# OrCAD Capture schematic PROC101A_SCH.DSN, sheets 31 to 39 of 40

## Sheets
31 40. HARDWARE SCHEMATICS: title: HARDWARE SCHEMATICS
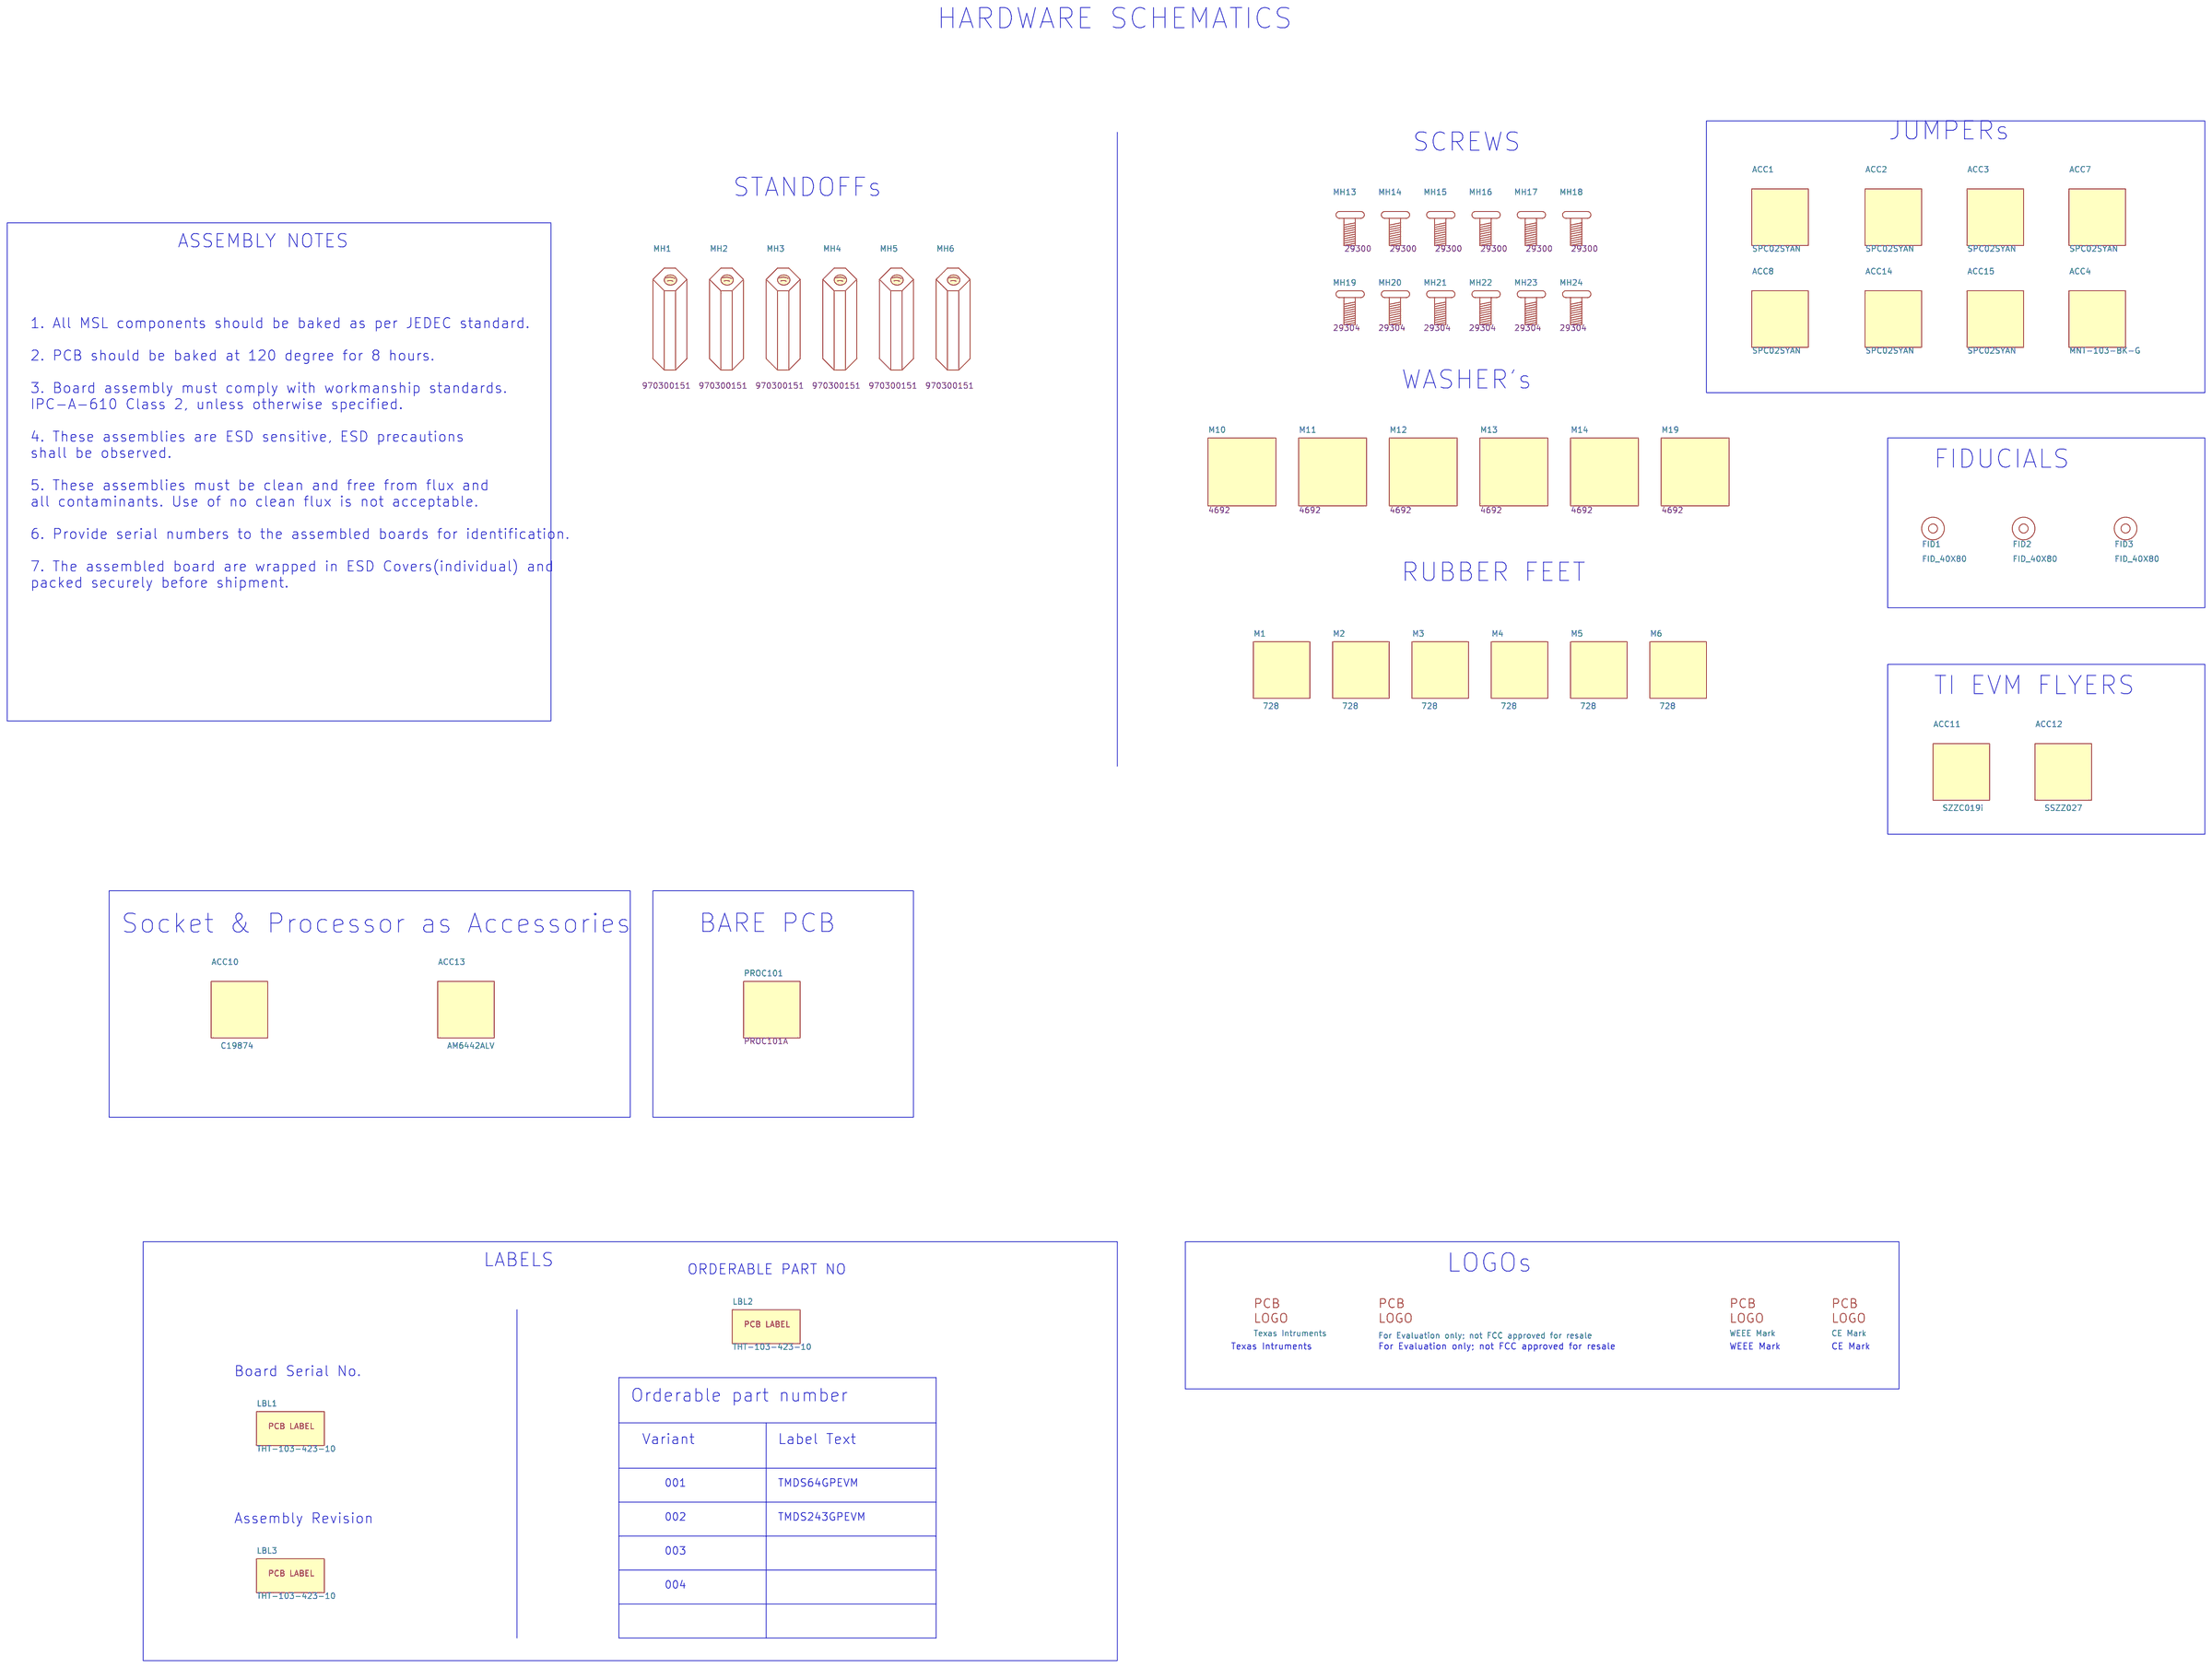
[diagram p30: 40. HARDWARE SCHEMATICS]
32 07. GPIO MAPPING TABLE: title: GPIO  MAPPING TABLE
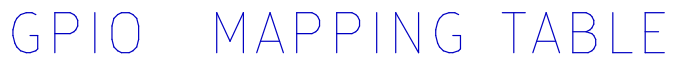
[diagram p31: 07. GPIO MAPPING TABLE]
33 08. I2C TREE: title: I2C TREE
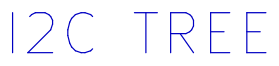
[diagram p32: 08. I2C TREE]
34 06. POWER SEQUENCE: title: POWER SEQUENCE
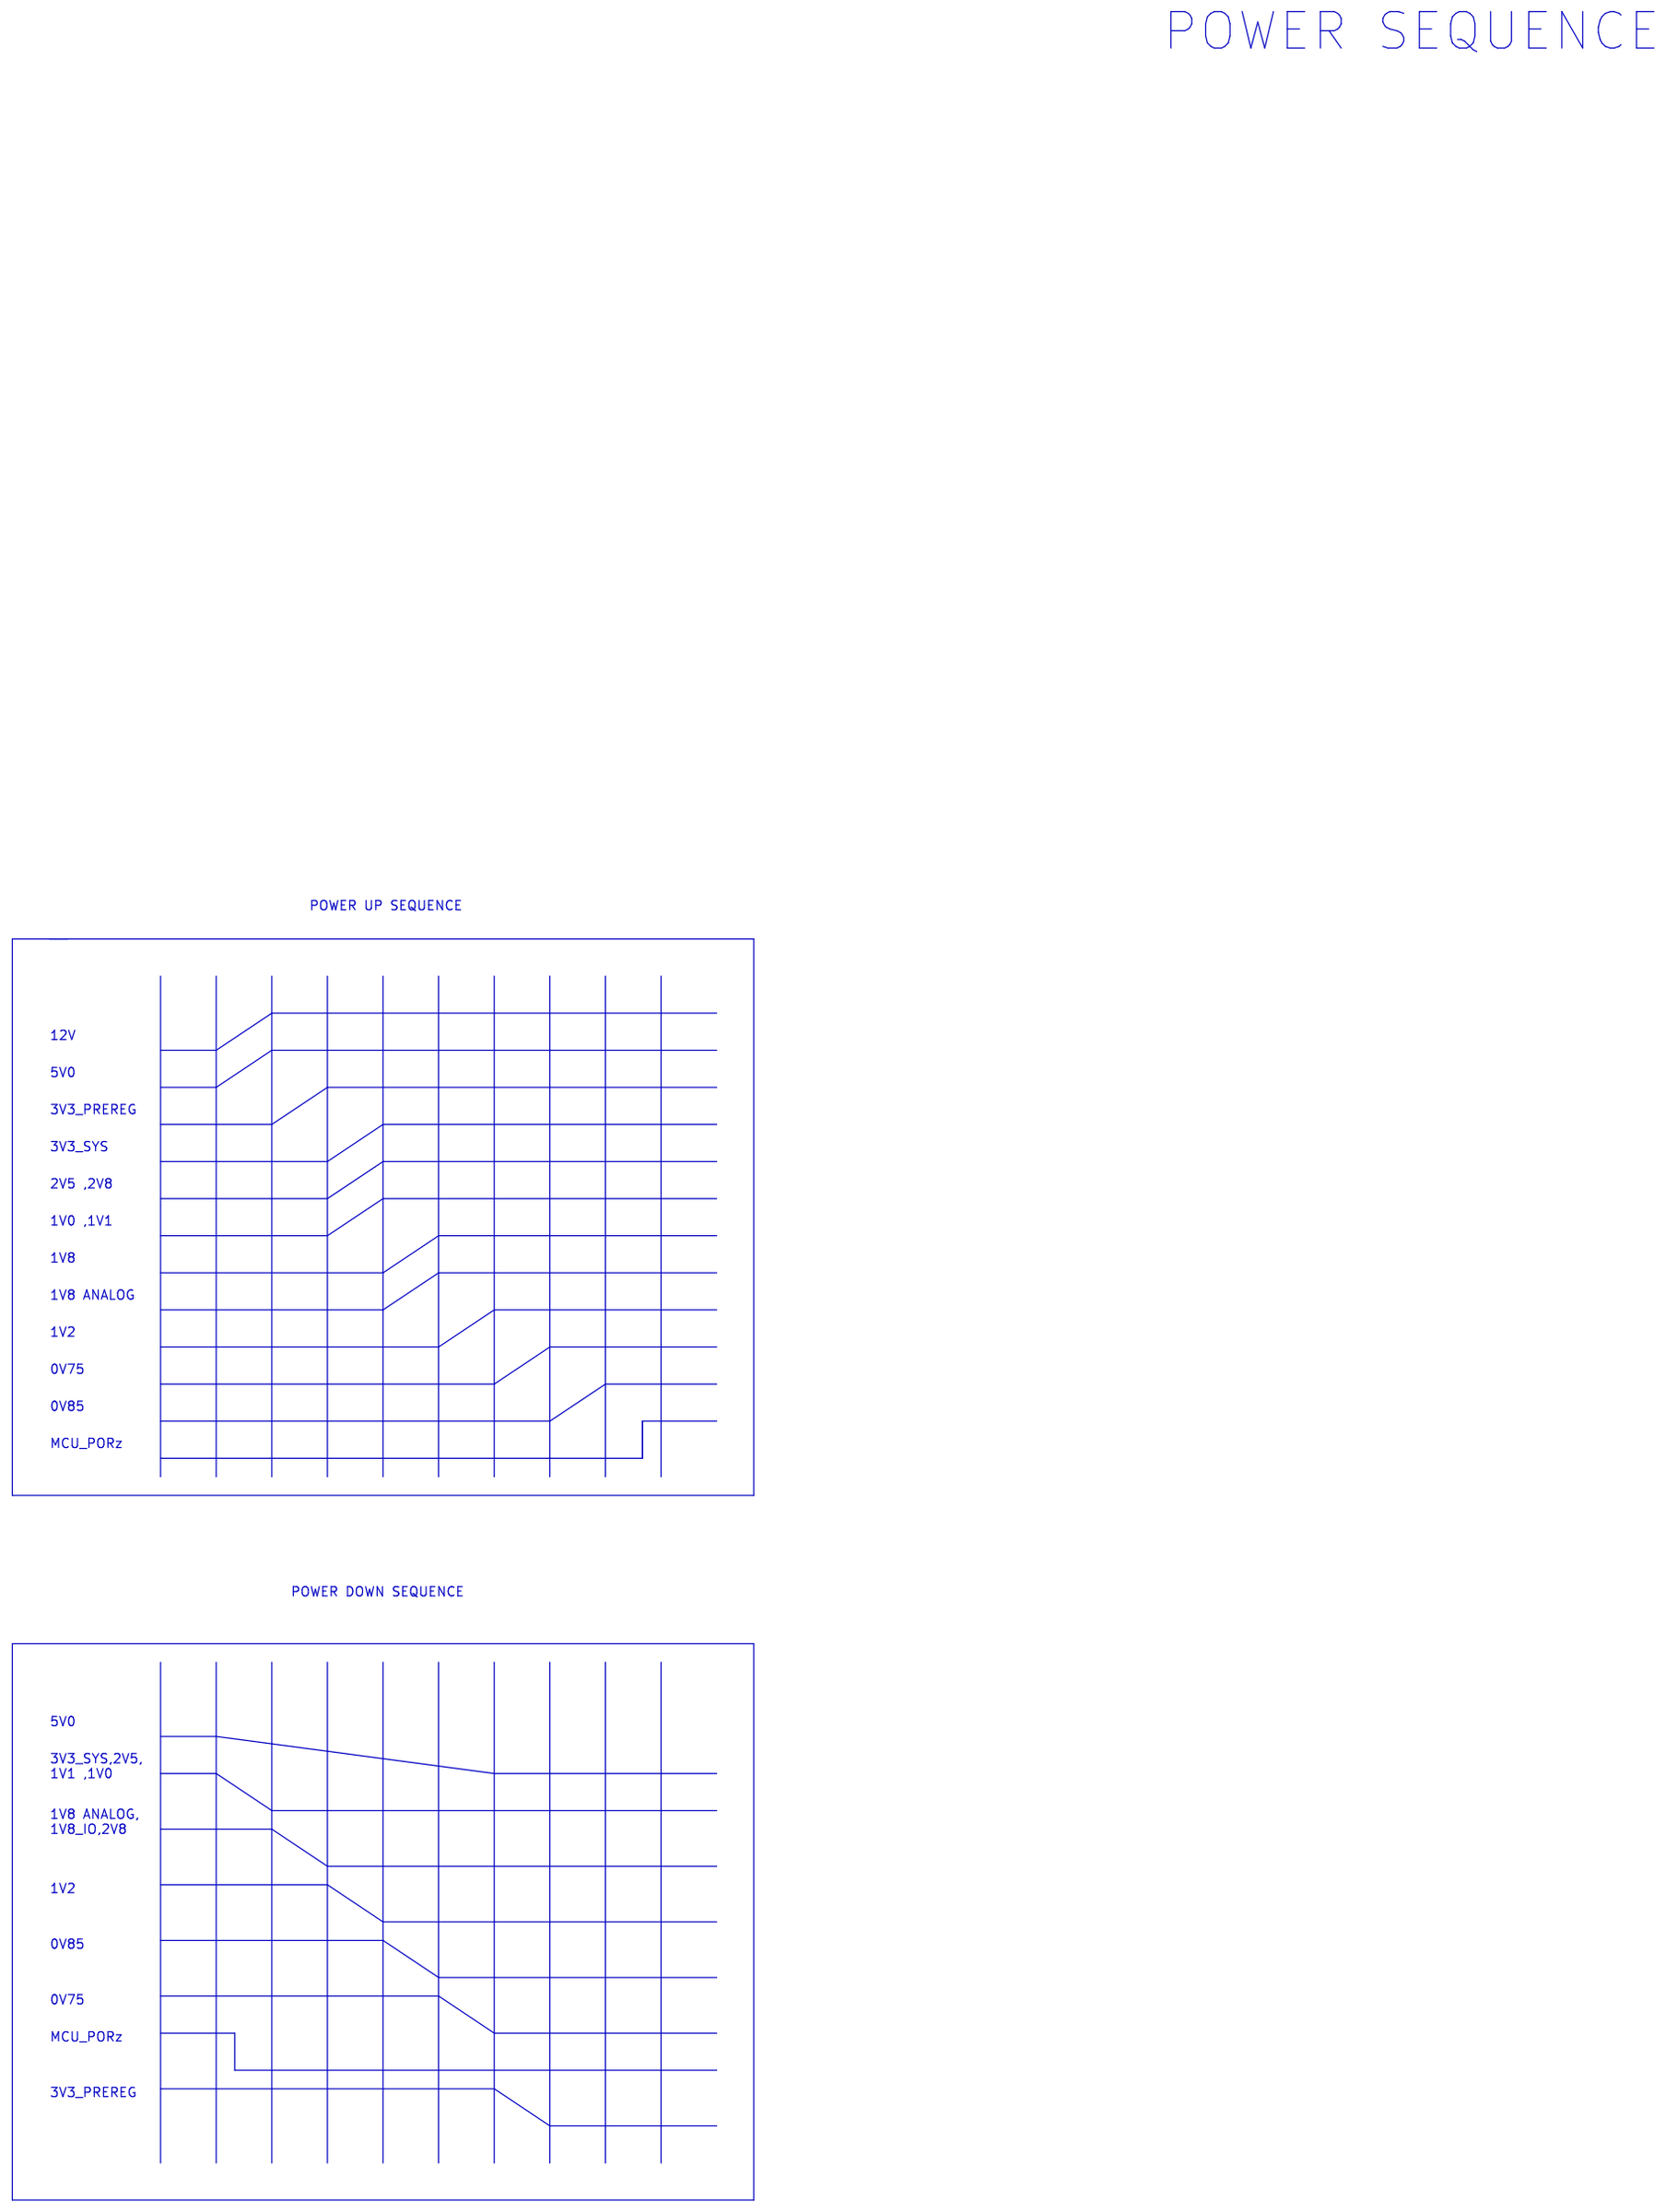
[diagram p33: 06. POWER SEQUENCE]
35 05. POWER FLOW DIAGRAM: title: POWER FLOW DIAGRAM
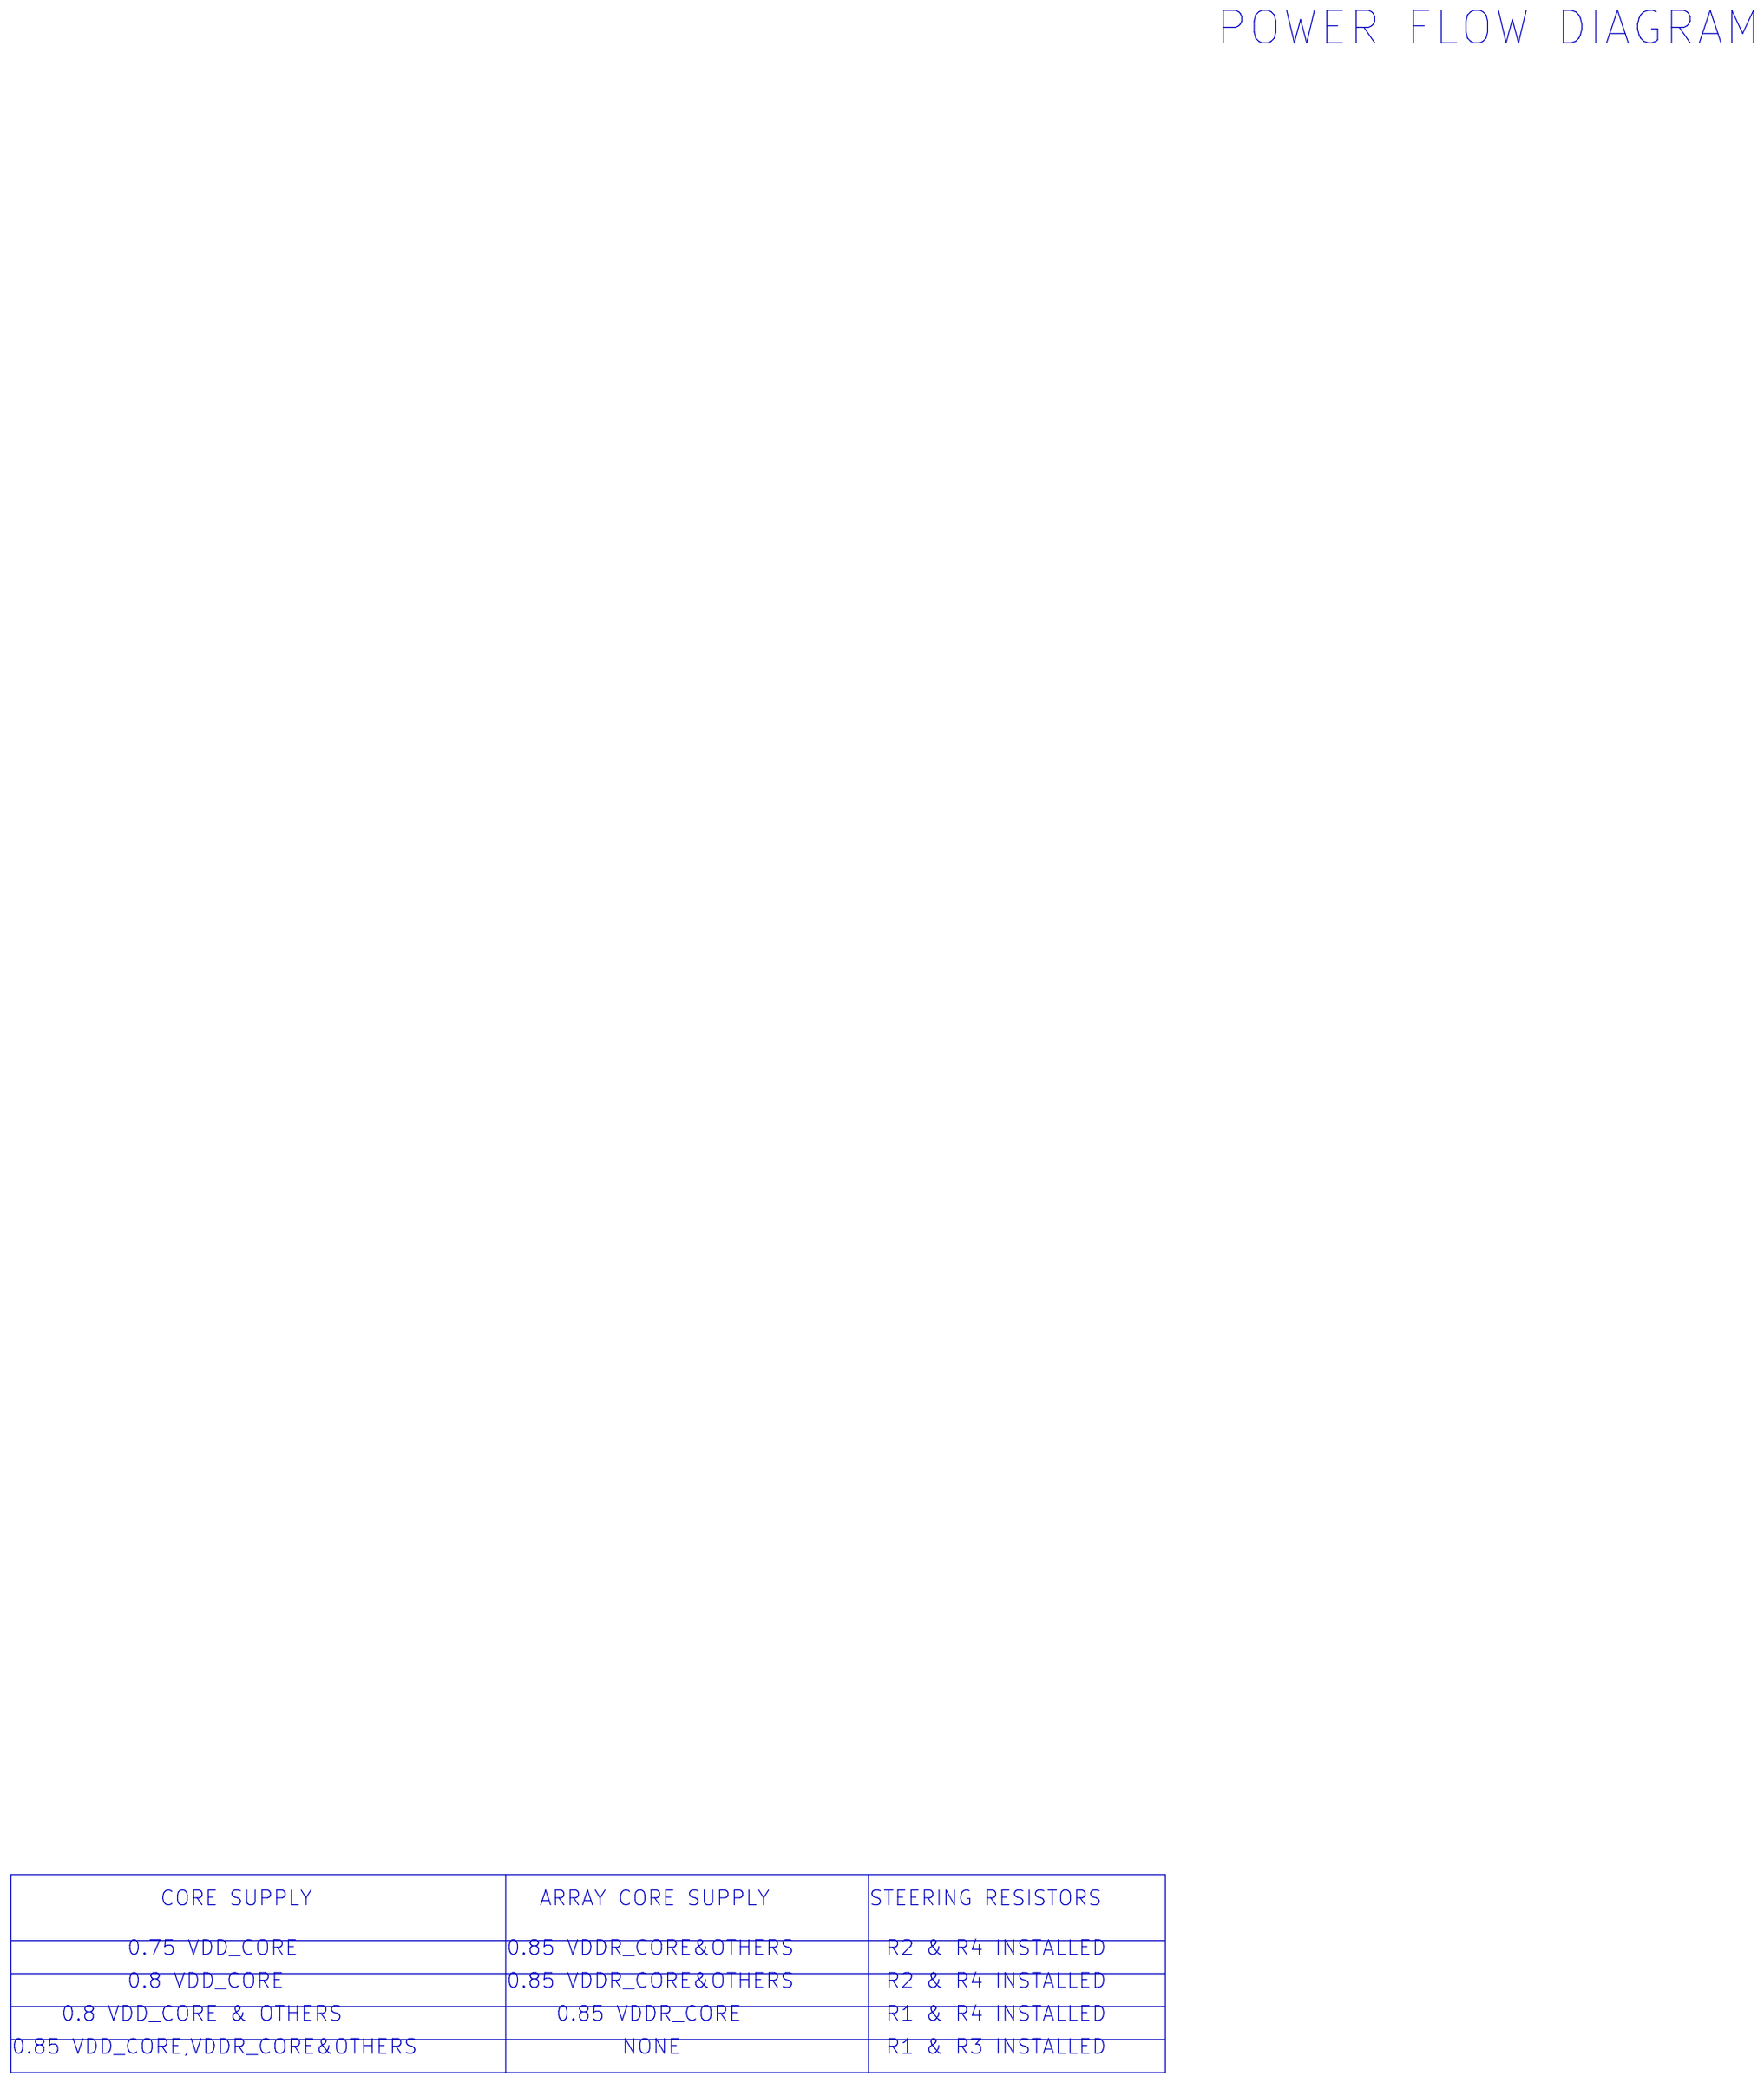
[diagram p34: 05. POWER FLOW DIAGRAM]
36 03.BLOCK_DIAGRAM_AM64x_EVM: title: BLOCK DIAGRAM_CP BOARD
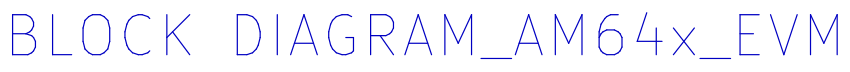
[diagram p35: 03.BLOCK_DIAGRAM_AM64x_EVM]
37 01. TABLE OF CONTENTS: title: TABLE OF CONTENTS
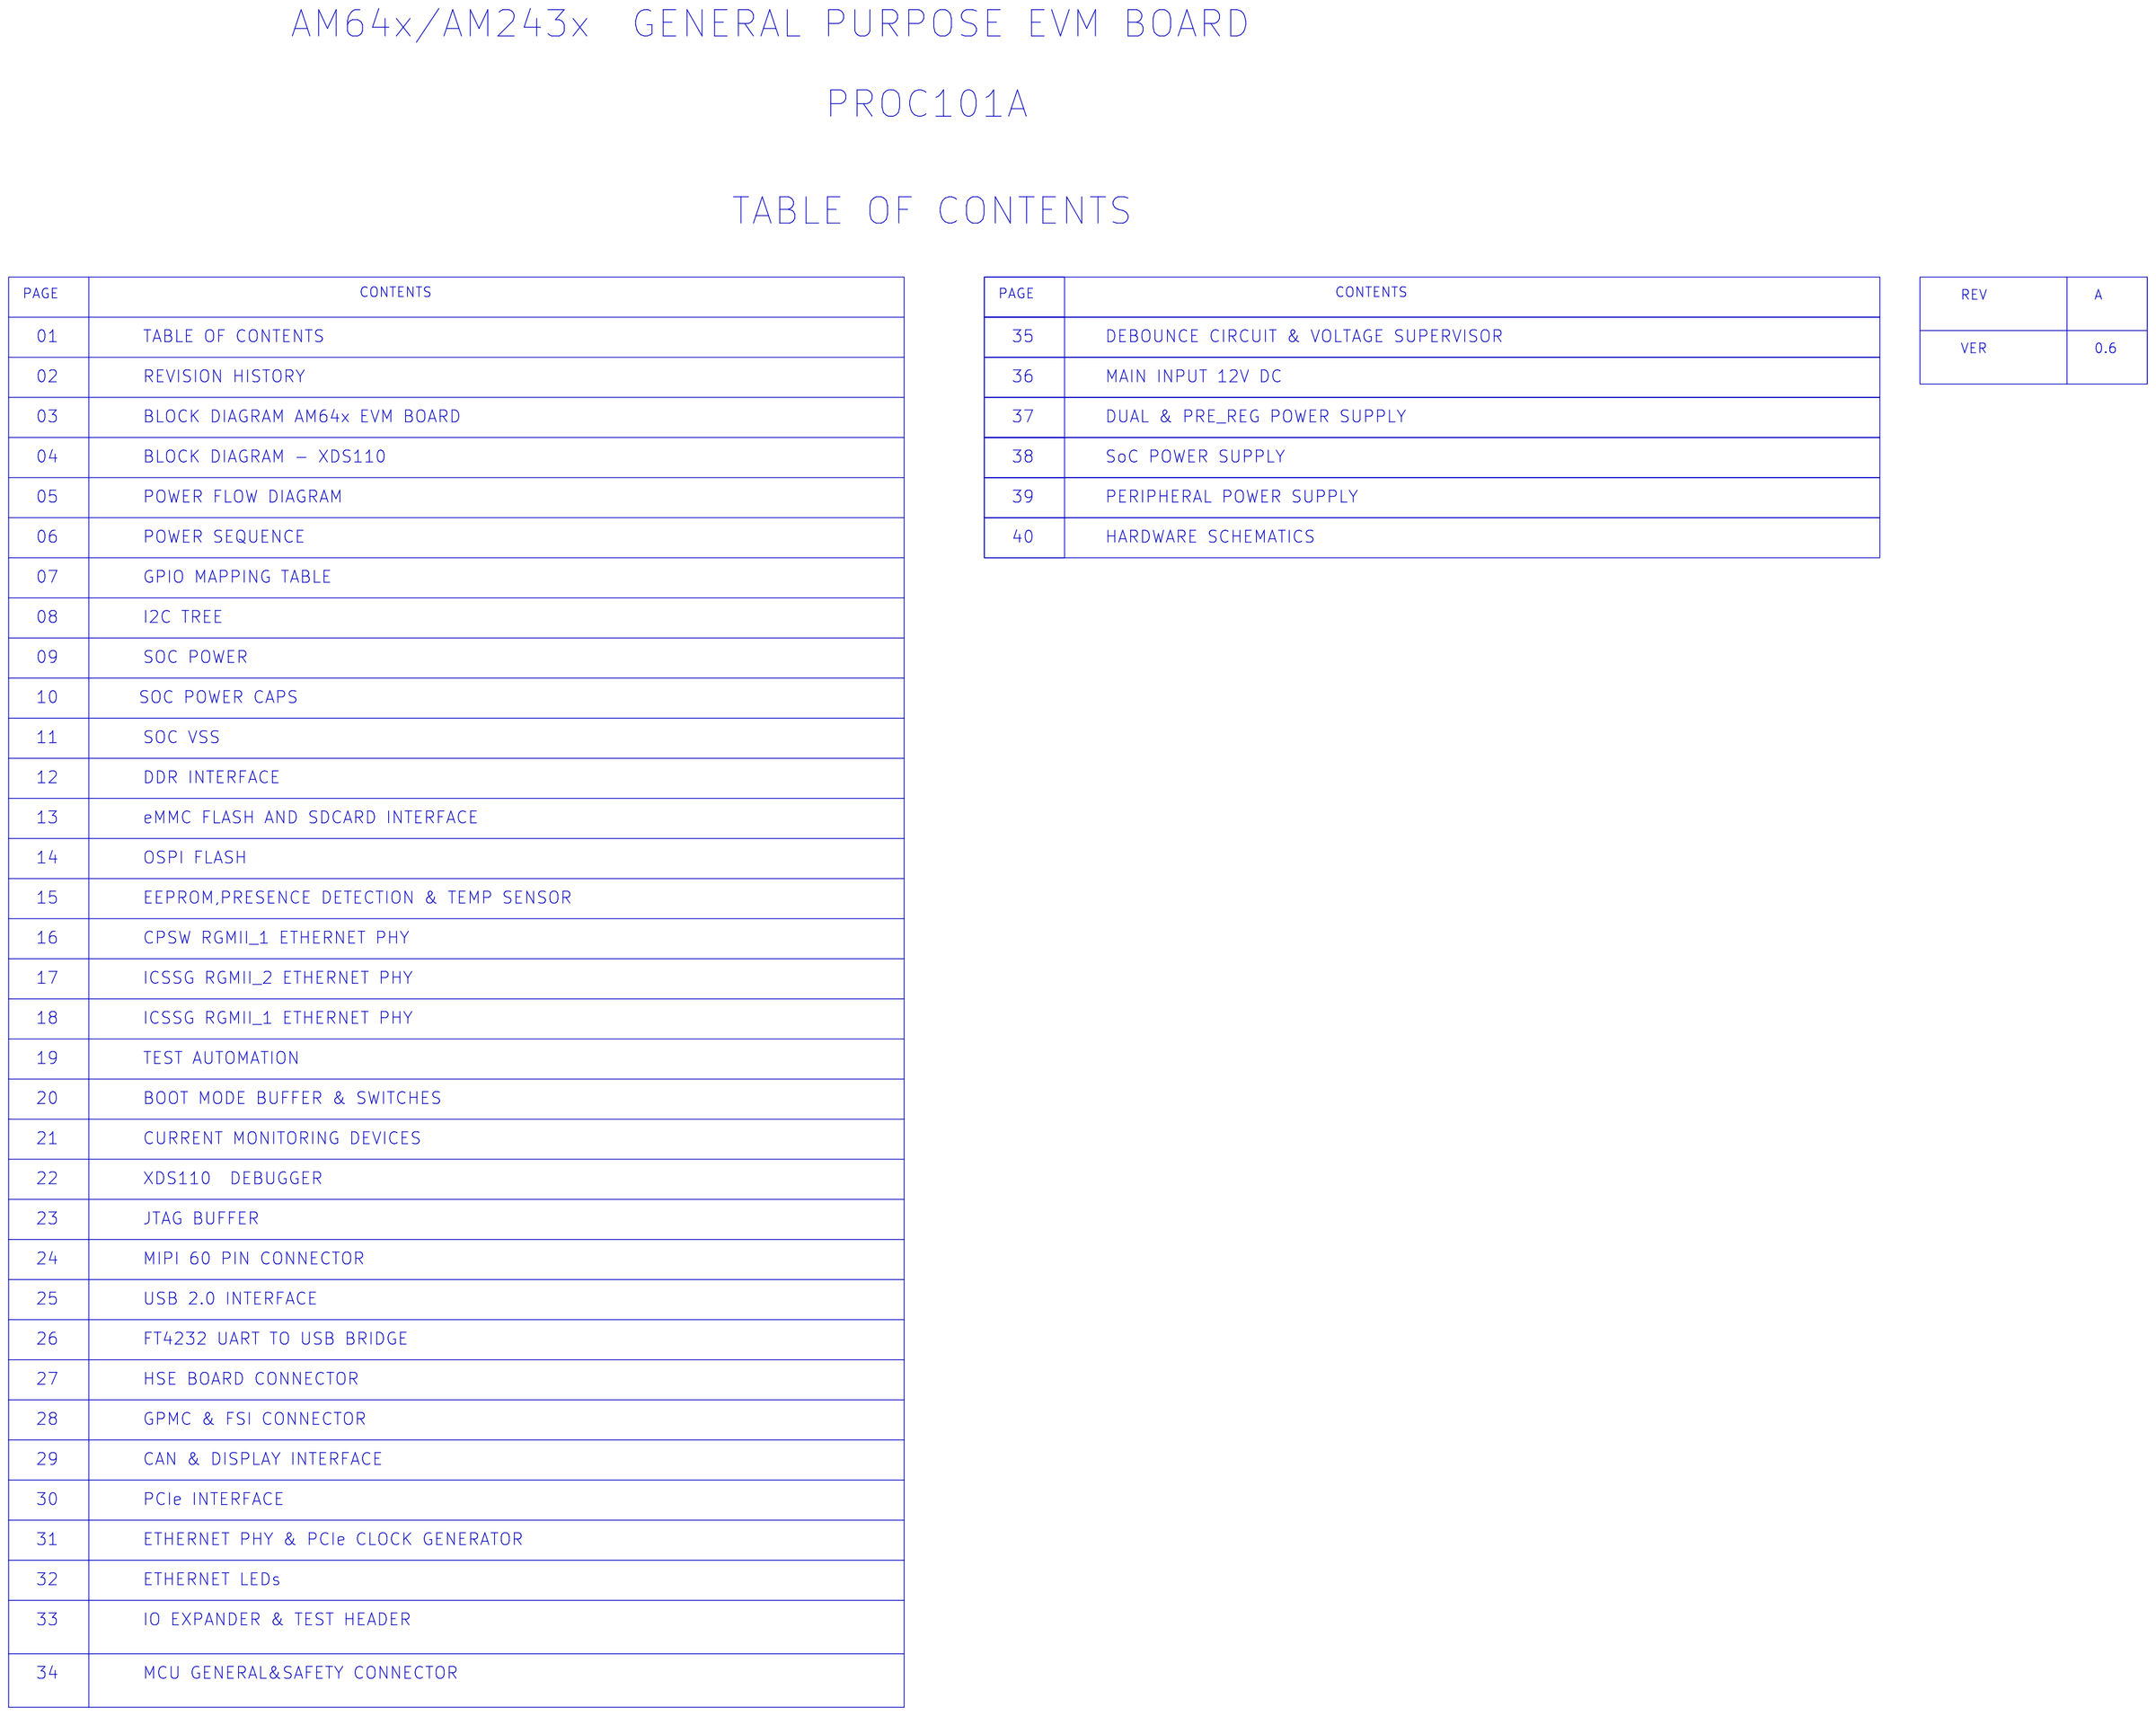
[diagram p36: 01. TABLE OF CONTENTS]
38 02. REVISION HISTORY: title: REVISION HISTORY
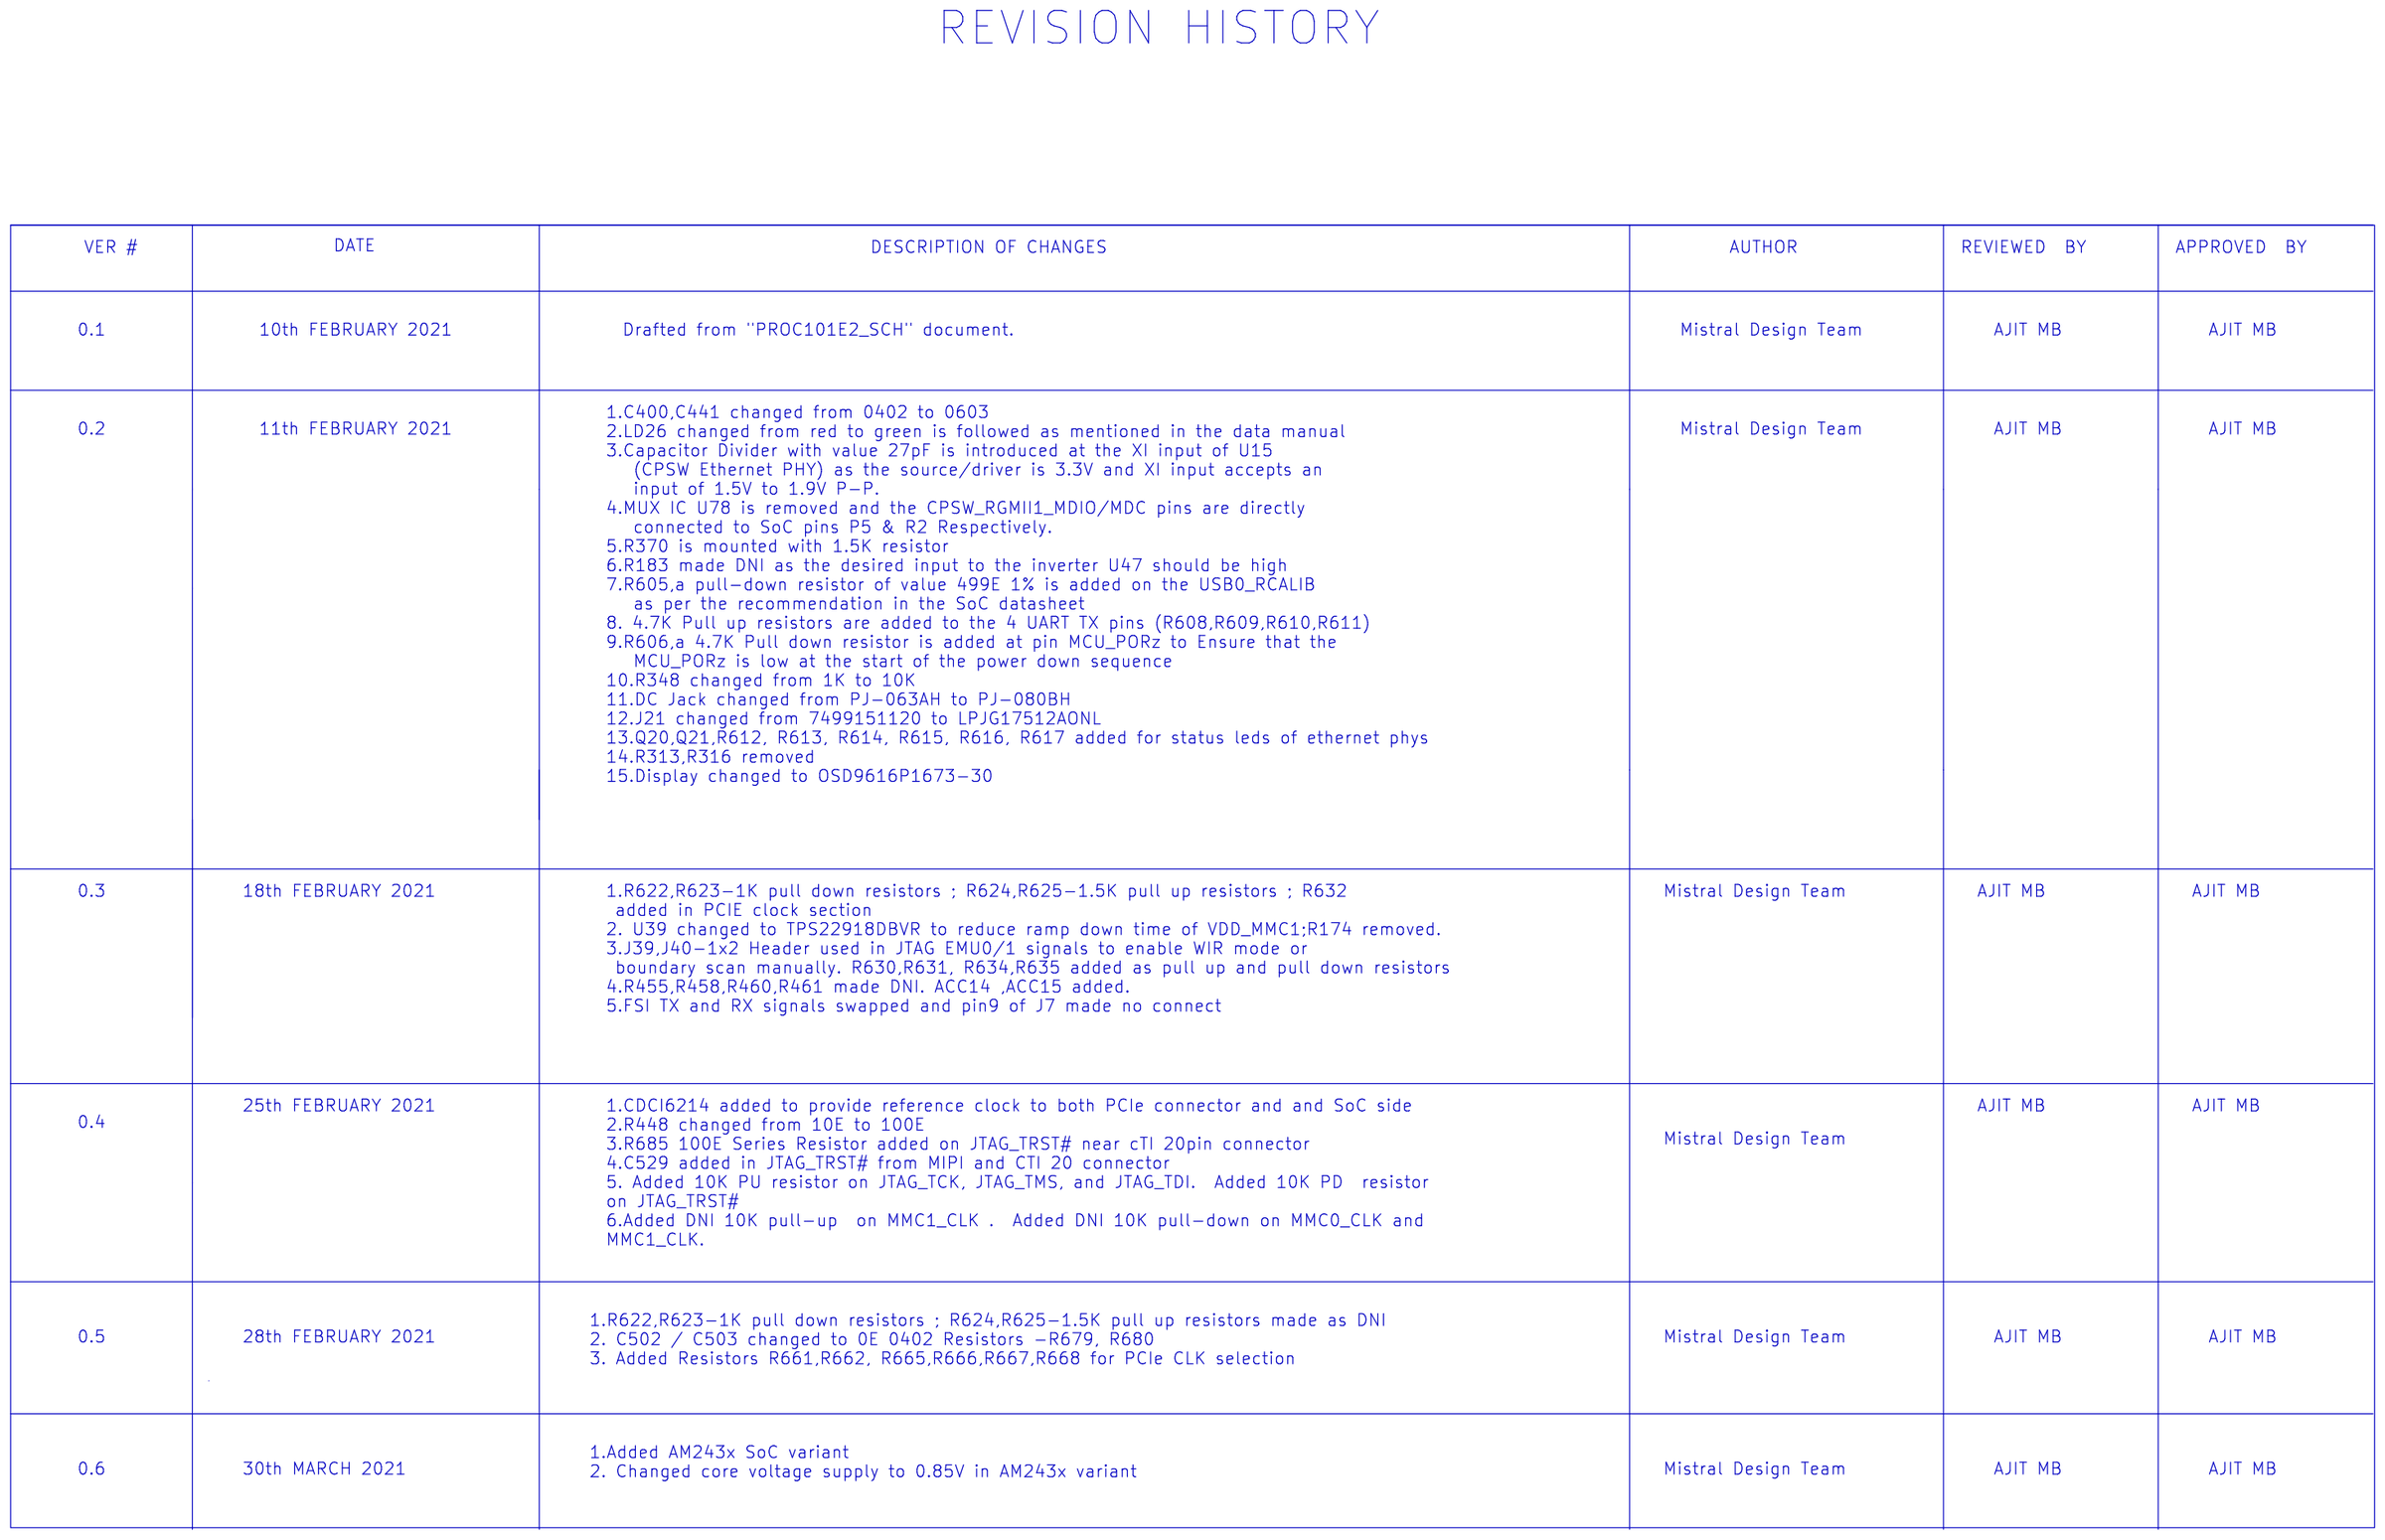
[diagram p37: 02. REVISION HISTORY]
39 17. ICSSG RGMII_2 ETHERNET PHY: size C; title: ICSSG1 RGMII_2 ETHERNET PHY
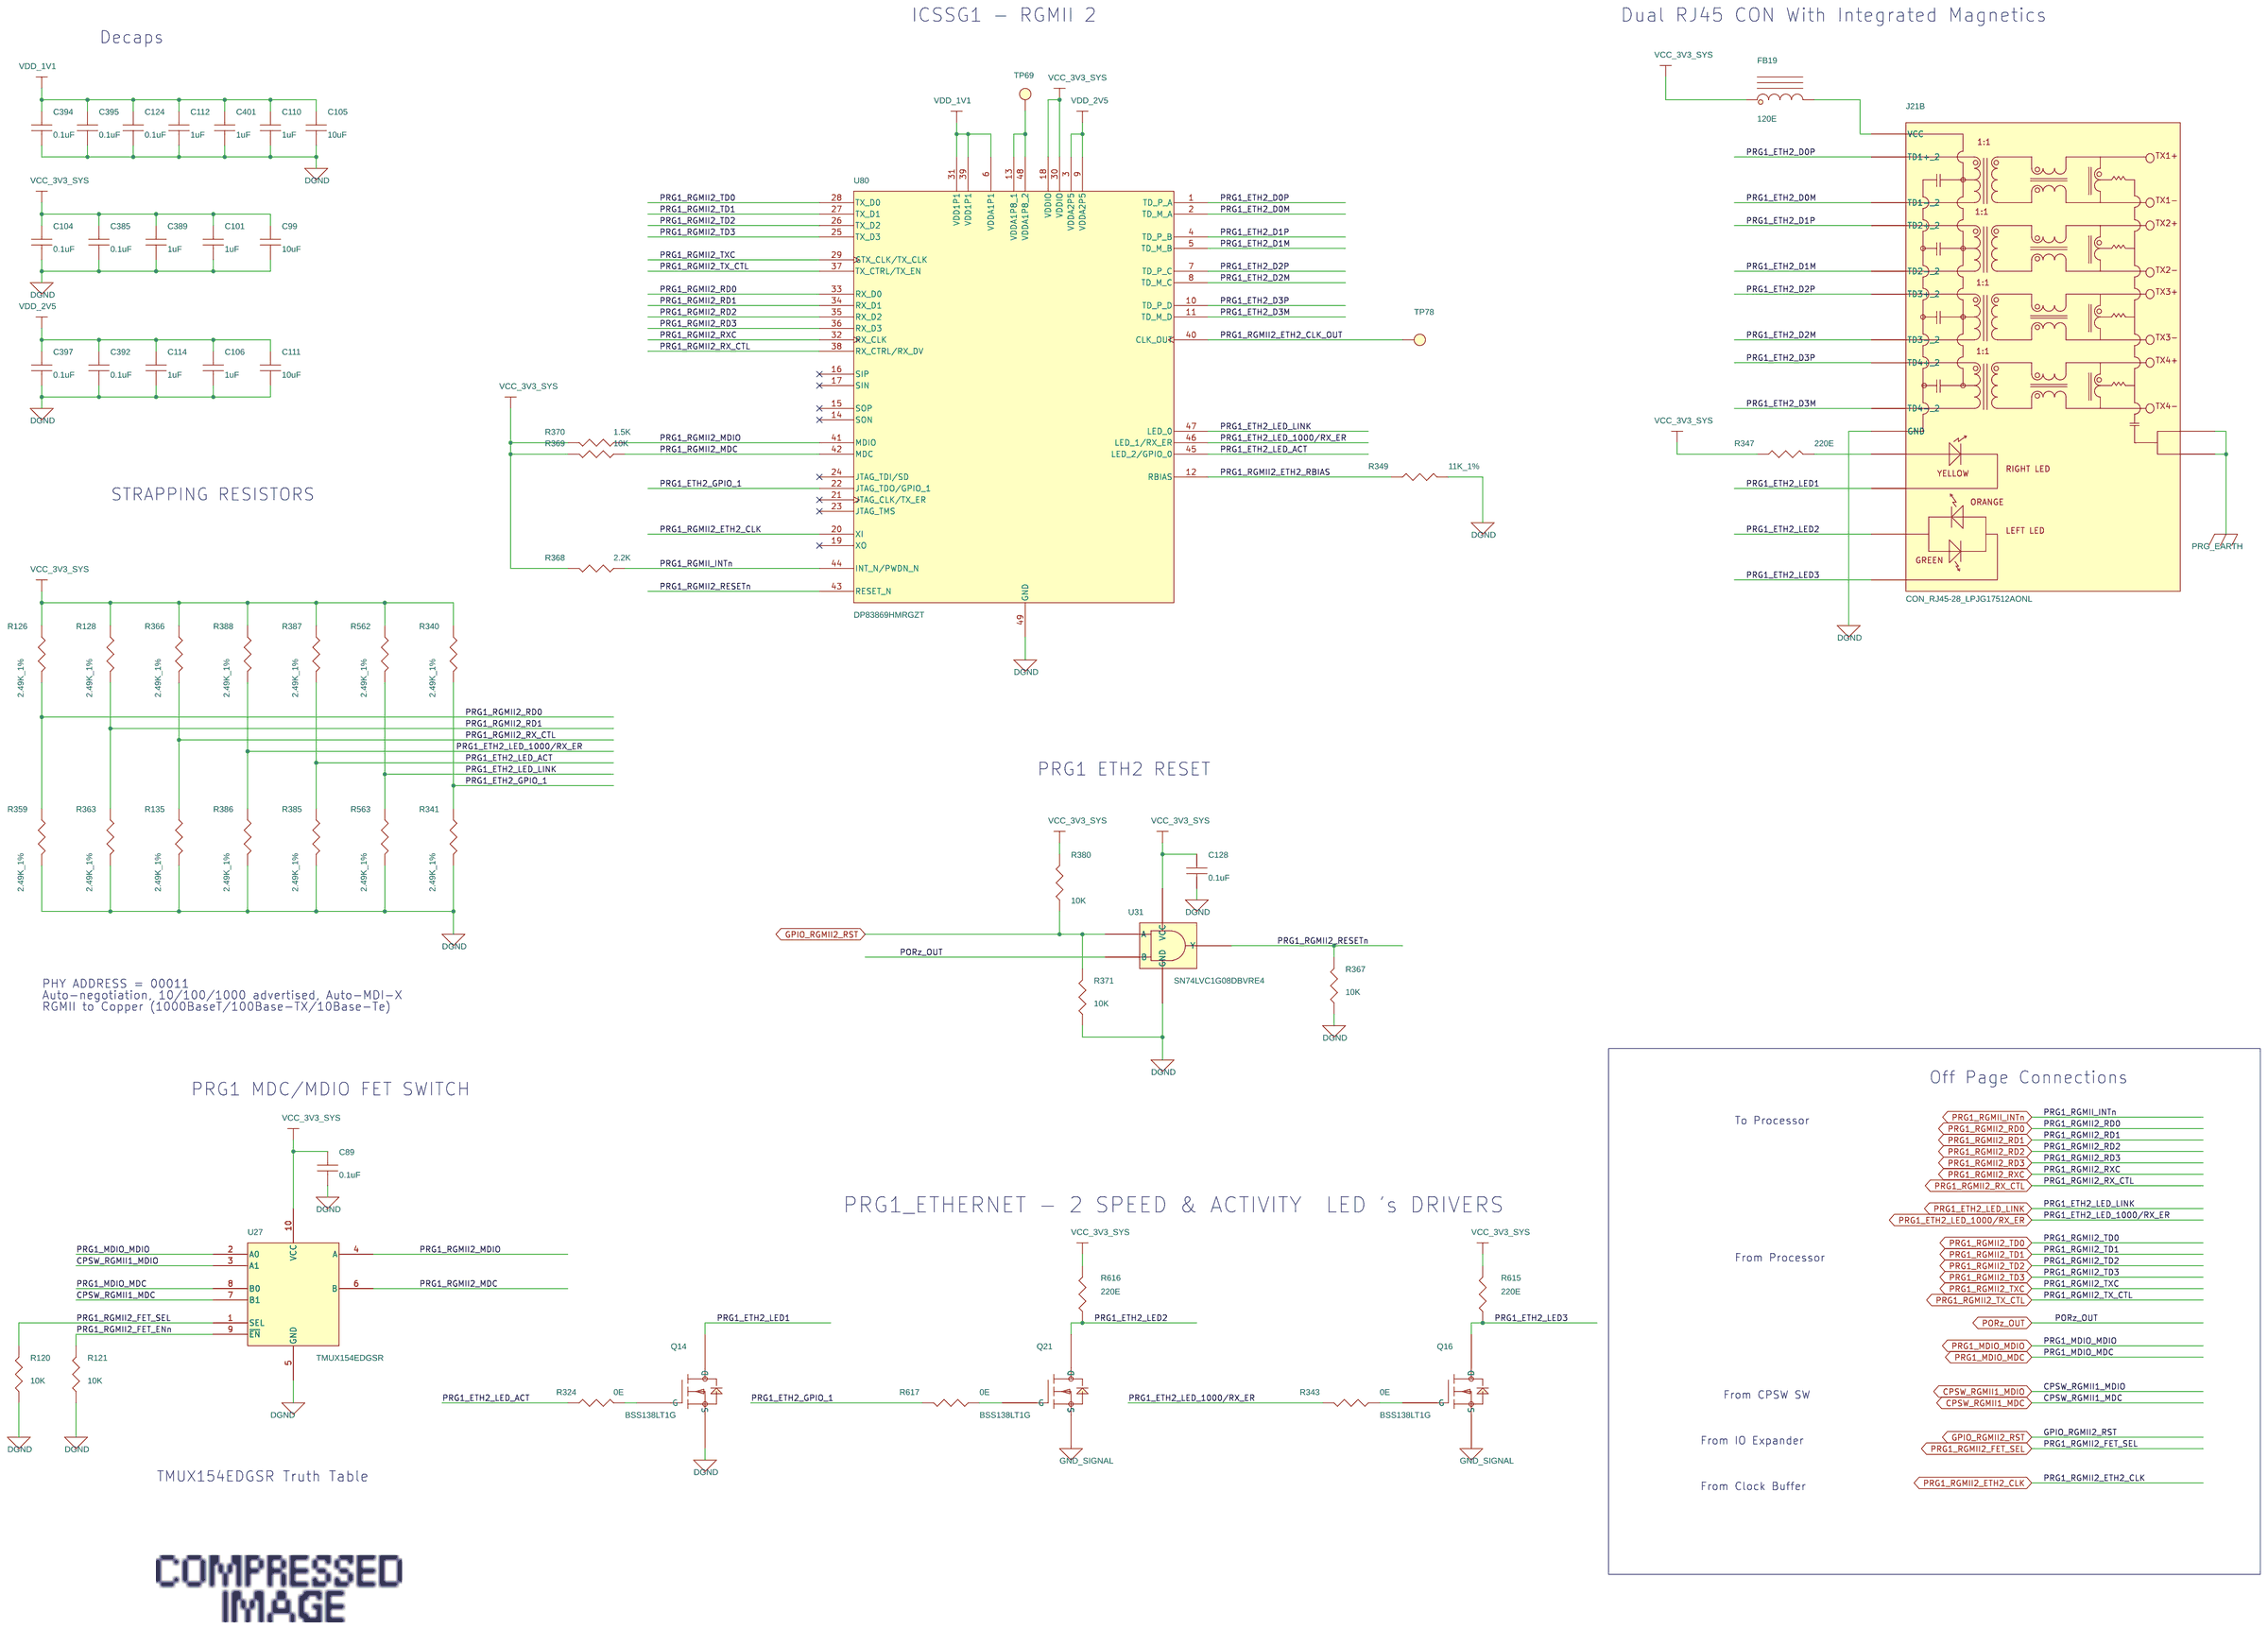
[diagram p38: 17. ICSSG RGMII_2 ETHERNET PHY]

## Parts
sheet 17. ICSSG RGMII_2 ETHERNET PHY
C89  0.1uF  [CAP0402_0-75]
C99  10uF  [CAP0402_0-75]
C101  1uF  [CAP0402_0-75]
C104  0.1uF  [CAP0402_0-75]
C105  10uF  [CAP0402_0-75]
C106  1uF  [CAP0402_0-75]
C110  1uF  [CAP0402_0-75]
C111  10uF  [CAP0402_0-75]
C112  1uF  [CAP0402_0-75]
C114  1uF  [CAP0402_0-75]
C124  0.1uF  [CAP0402_0-75]
C128  0.1uF  [CAP0402_0-75]
C385  0.1uF  [CAP0402_0-75]
C389  1uF  [CAP0402_0-75]
C392  0.1uF  [CAP0402_0-75]
C394  0.1uF  [CAP0402_0-75]
C395  0.1uF  [CAP0402_0-75]
C397  0.1uF  [CAP0402_0-75]
C401  1uF  [CAP0402_0-75]
FB19  120E  [IND0603_1]
J21  CON_RJ45-28_LPJG17512AONL  [CON_RJ45-28_LPJG17512_S_R_T_25-3]  (sections A,B)
Q14  BSS138LT1G  [SOT23-123_1-2]
Q16  BSS138LT1G  [SOT23-123_1-2]
Q21  BSS138LT1G  [SOT23-123_1-2]
R120  10K  [RES0402_0-5]
R121  10K  [RES0402_0-5]
R126  2.49K_1%  [RES0402_0-5]
R128  2.49K_1%  [RES0402_0-5]
R135  2.49K_1%  [RES0402_0-5]
R324  0E  [RES0402_0-5]
R340  2.49K_1%  [RES0402_0-5]
R341  2.49K_1%  [RES0402_0-5]
R343  0E  [RES0402_0-5]
R347  220E  [RES0402_0-5]
R349  11K_1%  [RES0402_0-5]
R359  2.49K_1%  [RES0402_0-5]
R363  2.49K_1%  [RES0402_0-5]
R366  2.49K_1%  [RES0402_0-5]
R367  10K  [RES0402_0-5]
R368  2.2K  [RES0402_0-5]
R369  10K  [RES0402_0-5]
R370  1.5K  [RES0402_0-5]
R371  10K  [RES0402_0-5]
R380  10K  [RES0402_0-5]
R385  2.49K_1%  [RES0402_0-5]
R386  2.49K_1%  [RES0402_0-5]
R387  2.49K_1%  [RES0402_0-5]
R388  2.49K_1%  [RES0402_0-5]
R562  2.49K_1%  [RES0402_0-5]
R563  2.49K_1%  [RES0402_0-5]
R615  220E  [RES0402_0-5]
R616  220E  [RES0402_0-5]
R617  0E  [RES0402_0-5]
TP69  TP20_SMD  [TP20_SMD]
TP78  TP20_SMD  [TP20_SMD]
U27  TMUX154EDGSR  [MSOP10_19-68_120X120_1-1]
U31  SN74LVC1G08DBVRE4  [SOT23-5]
U80  DP83869HMRGZT  [QFN48_19-68_280X280_1_EP4-2]
sheet 40. HARDWARE SCHEMATICS
ACC1  SPC02SYAN  [NA]
ACC2  SPC02SYAN  [NA]
ACC3  SPC02SYAN  [NA]
ACC4  MNT-103-BK-G  [NA]
ACC7  SPC02SYAN  [NA]
ACC8  SPC02SYAN  [NA]
ACC10  C19874  [BGASKT441_C19874_1190X1190_11]
ACC11  SZZC019i  [NA]
ACC12  SSZZ027  [NA]
ACC13  AM6442ALV
ACC14  SPC02SYAN  [NA]
ACC15  SPC02SYAN  [NA]
FID1  FID_40X80  [FID_40X80]
FID2  FID_40X80  [FID_40X80]
FID3  FID_40X80  [FID_40X80]
LBL1  THT-103-423-10  [NA]
LBL2  THT-103-423-10  [NA]
LBL3  THT-103-423-10  [NA]
Logo1  Texas Intruments  [TI_Stacked_Overlay_Small]
Logo2  For Evaluation only; not FCC approved for resale  [FCC_disclaimer]
Logo3  WEEE Mark  [TI_Stacked_Overlay_Small]
Logo4  CE Mark  [TI_Stacked_Overlay_Small]
M1  728  [NA]
M2  728  [NA]
M3  728  [NA]
M4  728  [NA]
M5  728  [NA]
M6  728  [NA]
M10  PLAIN WASHER_M3  [NA]
M11  PLAIN WASHER_M3  [NA]
M12  PLAIN WASHER_M3  [NA]
M13  PLAIN WASHER_M3  [NA]
M14  PLAIN WASHER_M3  [NA]
M19  PLAIN WASHER_M3  [NA]
MH1  HEX SPACER_M2.5 X 30  [NA]
MH2  HEX SPACER_M2.5 X 30  [NA]
MH3  HEX SPACER_M2.5 X 30  [NA]
MH4  HEX SPACER_M2.5 X 30  [NA]
MH5  HEX SPACER_M2.5 X 30  [NA]
MH6  HEX SPACER_M2.5 X 30  [NA]
MH13  PAN HEAD_M2.5 X 4  [NA]
MH14  PAN HEAD_M2.5 X 4  [NA]
MH15  PAN HEAD_M2.5 X 4  [NA]
MH16  PAN HEAD_M2.5 X 4  [NA]
MH17  PAN HEAD_M2.5 X 4  [NA]
MH18  PAN HEAD_M2.5 X 4  [NA]
MH19  PAN HEAD_M2.5 X 12  [NA]
MH20  PAN HEAD_M2.5 X 12  [NA]
MH21  PAN HEAD_M2.5 X 12  [NA]
MH22  PAN HEAD_M2.5 X 12  [NA]
MH23  PAN HEAD_M2.5 X 12  [NA]
MH24  PAN HEAD_M2.5 X 12  [NA]
PCB1  PROC101

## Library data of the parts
C89 C104 C124 C128 C385 C392 C394 C395 C397 = CAP: CAP CERAMIC 0.1uF 25V 20% X5R 0402; Alt_Mfr_name: YAGEO AMERICA; Alt_Mfr_part_number: CC0402KRX5R8BB104; Chkd/date: MANIRAJA/170820; Crtd /date: ALVY/170820; Custom_Duty: 15%; Customs_HS_Code: 85322990; Distributor_name: DIGIKEY; Distributor_part_number: 732-7495-1-ND; Footprint Path: Y:\MIS_DATABASE\Library\ALTIUM_TOOL\PCB_FOOTPRINTS\Altium_Footprint_Lib.PcbLib; Height: 0.55MM; Library Path: Y:\MIS_DATABASE\Library\ALTIUM_TOOL\SCHEMATICS_PARTS\MS_DISCRETE_Library.schlib; Mfr_name: WURTH ELECTRONICS; Mfr_part_number: 885012105018; Mistral Part No: 120020080003-R; Package: 0402; Part_type: CAPACITORS\CERAMIC; Project: AM64x_EVM_BRD; RoHS: RoHS; Temperature: -55°C+85°C; Tolerance: 20%; Voltage: 25V; Wattage: NA; Weight: 0.65mg; Datasheet: Y:\MIS_DATABASE\DATASHEETS\CAPACITORS\885012105018.PDF
C99 C105 C111 = CAP: CAP CERAMIC 10uF 10V 20% X5R 0402; Chkd/date: MANIRAJA/300520; Crtd /date: ALVY/260520; Custom_Duty: 15%; Customs_HS_Code: 85322990; Distributor_name: DIGIKEY; Distributor_part_number: 490-GRM155R61A106ME11DTR-ND; Footprint Path: Y:\MIS_DATABASE\Library\ALTIUM_TOOL\PCB_FOOTPRINTS\Altium_Footprint_Lib.PcbLib; Height: 0.55MM; Library Path: Y:\MIS_DATABASE\Library\ALTIUM_TOOL\SCHEMATICS_PARTS\MS_DISCRETE_Library.schlib; Mfr_name: MURATA; Mfr_part_number: GRM155R61A106ME11D; Mistral Part No: 120013110019-R; Package: 0402; Part_type: CAPACITORS\CERAMIC; Project: QCS610_NANOSOM; RoHS: RoHS; Temperature: -55°C+85°C; Tolerance: 20%; Voltage: 10V; Wattage: NA; Weight: 3.1mg; Datasheet: Y:\MIS_DATABASE\DATASHEETS\CAPACITORS\MURATA-GXX-SER_NOV17.PDF
C101 C106 C110 C112 C114 C389 C401 = CAP: CAP CERAMIC 1uF 10V 20% X5R 0402; Chkd/date: MANIRAJA/210820; Crtd /date: ALVY/190820; Custom_Duty: 15%; Customs_HS_Code: 85322990; Distributor_name: DIGIKEY; Distributor_part_number: 732-7489-1-ND; Footprint Path: Y:\MIS_DATABASE\Library\ALTIUM_TOOL\PCB_FOOTPRINTS\Altium_Footprint_Lib.PcbLib; Height: 0.55MM; Library Path: Y:\MIS_DATABASE\Library\ALTIUM_TOOL\SCHEMATICS_PARTS\MS_DISCRETE_Library.schlib; Mfr_name: WURTH ELECTRONICS; Mfr_part_number: 885012105012; Mistral Part No: 120020080009-R; Package: 0402; Part_type: CAPACITORS\CERAMIC; Project: AM64x_EVM_BRD; RoHS: RoHS; Temperature: -55°C+85°C; Tolerance: 20%; Voltage: 10V; Wattage: NA; Weight: 0.65mg; Datasheet: Y:\MIS_DATABASE\DATASHEETS\CAPACITORS\885012105012.PDF
FB19 = INDUCTOR_FERRITE: IND FERRITE BEAD CHIP 120E 2A 0603; Chkd/date: MANIRAJA/180820; Crtd /date: ALVY/180820; Custom_Duty: 24%; Customs_HS_Code: 85437099; Distributor_name: DIGIKEY; Distributor_part_number: 732-782631141CT-ND; Footprint Path: Y:\MIS_DATABASE\Library\ALTIUM_TOOL\PCB_FOOTPRINTS\Altium_Footprint_Lib.PcbLib; Height: 1.00MM; Library Path: Y:\MIS_DATABASE\Library\ALTIUM_TOOL\SCHEMATICS_PARTS\MS_FILTER_Library.schlib; Mfr_name: WURTH ELECTRONICS; Mfr_part_number: 782631141; Mistral Part No: 130020080015-R; Package: 0603; Part_type: INDUCTOR; Project: AM64x_EVM_BRD; RoHS: RoHS; Temperature: -55°C+125°C; Tolerance: 25%; Voltage: NA; Wattage: NA; Weight: NA; Datasheet: Y:\MIS_DATABASE\DATASHEETS\DISCRETES\INDUCTORS\782631141.PDF
J21 = CON_RJ45-28_LPJG17512AONL: CON JACK RJ45 28POS REGISTERED FEMALE RA TH; Chkd/date: MANIRAJA/010817; Crtd /date: MANIRAJA/010817; Custom_Duty: 24%; Customs_HS_Code: 85369090; Distributor_name: NA; Distributor_part_number: NA; Height: 25.30MM; Mfr_name: LINK-PP; Mfr_part_number: LPJG17512AONL; Mistral Part No: 150017080001-R; Package: THRU-HOLE; Part_type: CONNECTOR\JACK; Project: TI_SVB_DUT; RoHS: RoHS; Temperature: 0°C+70°C; Tolerance: NA; Voltage: NA; Wattage: NA; Weight: NA; Datasheet: Y:\MIS_DATABASE\DATASHEETS\CONNECTORS\LPJG17512AONL.PDF
Q14 Q16 Q21 = MOSFET_BSS138LT1G: IC MOSFET N-CHANNEL 50V 200mA SOT23-3; Chkd/date: MANIRAJA/250219; Crtd /date: JEBRAN/060416; Custom_Duty: 15%; Customs_HS_Code: 85423100; Distributor_name: DIGIKEY; Distributor_part_number: BSS138LT1GOSCT-ND; Footprint Path: Y:\MIS_DATABASE\Library\ALTIUM_TOOL\PCB_FOOTPRINTS\Altium_Footprint_Lib.PcbLib; Height: 1.11MM; Library Path: Y:\MIS_DATABASE\Library\ALTIUM_TOOL\SCHEMATICS_PARTS\MS_MOSFET_Library.schlib; Library Ref: MOSFET_BSS138W; Mfr_name: ON SEMICONDUCTOR; Mistral Part No: 142016040001-R; Package: SOT23-3; Part_type: ICS\POWER\MOSFET; Project: LRDE_ABCM; RoHS: RoHS; Temperature: -55°C+150°C; Tolerance: NA; Voltage: NA; Wattage: NA; Weight: 8mg; Datasheet: Y:\MIS_DATABASE\DATASHEETS\DISCRETES\TRANSISTORS_FETS\BSS138LT1G.PDF
R120 R121 R367 R369 R371 R380 = RESISTOR: RES 10K 1/16W 5% 0402; Chkd/date: VASANTHA/061216; Crtd /date: MAZHAR/230805; Custom_Duty: 15%; Customs_HS_Code: 85332119; Distributor_name: DIGIKEY; Distributor_part_number: 311-10KJRCT-ND; Footprint Path: Y:\MIS_DATABASE\Library\ALTIUM_TOOL\PCB_FOOTPRINTS\Altium_Footprint_Lib.PcbLib; Height: 0.40MM; Library Path: Y:\MIS_DATABASE\Library\ALTIUM_TOOL\SCHEMATICS_PARTS\MS_DISCRETE_Library.schlib; Mfr_name: YAGEO AMERICA; Mfr_part_number: RC0402JR-0710KL; Mistral Part No: 110011060021-R; Package: 0402; Part_type: RESISTORS\FIXED; Project: HSE; RoHS: RoHS; Temperature: -55°C+155°C; Tolerance: 5%; Voltage: NA; Wattage: 1/16W; Weight: 0.65mg; Datasheet: Y:\MIS_DATABASE\DATASHEETS\RESISTORS\RCXXXXL-SER_MAR18.PDF
R126 R128 R135 R340 R341 R359 R363 R366 R385-R388 R562 R563 = RESISTOR: RES 2.49K 1/16W 1% 0402; Chkd/date: VASANTHA/270516; Crtd /date: VASANTHA/270516; Custom_Duty: 15%; Customs_HS_Code: 85332119; Distributor_name: DIGIKEY; Distributor_part_number: 311-2.49KLRCT-ND; Footprint Path: Y:\MIS_DATABASE\Library\ALTIUM_TOOL\PCB_FOOTPRINTS\Altium_Footprint_Lib.PcbLib; Height: 0.40MM; Library Path: Y:\MIS_DATABASE\Library\ALTIUM_TOOL\SCHEMATICS_PARTS\MS_DISCRETE_Library.schlib; Mfr_name: YAGEO AMERICA; Mfr_part_number: RC0402FR-072K49L; Mistral Part No: 110016050020-R; Package: 0402; Part_type: RESISTORS\FIXED; Project: TMDXCSKCC; RoHS: RoHS; Temperature: -55°C+155°C; Tolerance: 1%; Voltage: NA; Wattage: 1/16W; Weight: 0.65mg; Datasheet: Y:\MIS_DATABASE\DATASHEETS\RESISTORS\RCXXXXL-SER_MAR18.PDF
R324 R343 R617 = RESISTOR: RES 0E 1/16W JUMPER 0402; Chkd/date: VASANTHA/201216; Crtd /date: MUDDU/190810; Custom_Duty: 15%; Customs_HS_Code: 85332119; Distributor_name: DIGIKEY; Distributor_part_number: 541-0.0JCT-ND; Footprint Path: Y:\MIS_DATABASE\Library\ALTIUM_TOOL\PCB_FOOTPRINTS\Altium_Footprint_Lib.PcbLib; Height: 0.40MM; Library Path: Y:\MIS_DATABASE\Library\ALTIUM_TOOL\SCHEMATICS_PARTS\MS_DISCRETE_Library.schlib; Mfr_name: VISHAY; Mfr_part_number: CRCW04020000Z0ED; Mistral Part No: 110010080019-R; Package: 0402; Part_type: RESISTORS\FIXED; Project: PB_BUGBASE; RoHS: RoHS; Temperature: -55°C+155°C; Tolerance: NA; Voltage: NA; Wattage: 1/16W; Weight: 0.65mg; Datasheet: Y:\MIS_DATABASE\DATASHEETS\RESISTORS\CRCW0603.PDF
R347 R615 R616 = RESISTOR: RES 220E 1/10W 5% 0402; Chkd/date: VASANTHA/291216; Crtd /date: GEETHA/260406; Custom_Duty: 15%; Customs_HS_Code: 85332119; Distributor_name: DIGIKEY; Distributor_part_number: P220JCT-ND; Footprint Path: Y:\MIS_DATABASE\Library\ALTIUM_TOOL\PCB_FOOTPRINTS\Altium_Footprint_Lib.PcbLib; Height: 0.40MM; Library Path: Y:\MIS_DATABASE\Library\ALTIUM_TOOL\SCHEMATICS_PARTS\MS_DISCRETE_Library.schlib; Mfr_name: PANASONIC-ECG; Mfr_part_number: ERJ-2GEJ221X; Mistral Part No: 110009030506-R; Package: 0402; Part_type: RESISTORS\FIXED; Project: RED EYE; RoHS: RoHS; Temperature: -55°C+155°C; Tolerance: 5%; Voltage: NA; Wattage: 1/10W; Weight: 0.8mg; Datasheet: Y:\MIS_DATABASE\DATASHEETS\RESISTORS\PAN-ERJSER_NOV17.PDF
R349 = RESISTOR: RES 11K 1/16W 1% 0402; Chkd/date: VASANTHA/251115; Crtd /date: VASANTHA/251115; Custom_Duty: 15%; Customs_HS_Code: 85332119; Distributor_name: DIGIKEY; Distributor_part_number: 311-11.0KLRCT-ND; Footprint Path: Y:\MIS_DATABASE\Library\ALTIUM_TOOL\PCB_FOOTPRINTS\Altium_Footprint_Lib.PcbLib; Height: 0.40MM; Library Path: Y:\MIS_DATABASE\Library\ALTIUM_TOOL\SCHEMATICS_PARTS\MS_DISCRETE_Library.schlib; Mfr_name: YAGEO AMERICA; Mfr_part_number: RC0402FR-0711KL; Mistral Part No: 110015110012-R; Package: 0402; Part_type: RESISTORS\FIXED; Project: TI_VLAN_SWITCH; RoHS: RoHS; Temperature: -55°C+155°C; Tolerance: 1%; Voltage: NA; Wattage: 1/16W; Weight: 0.65mg; Datasheet: Y:\MIS_DATABASE\DATASHEETS\RESISTORS\RCXXXXL-SER_MAR18.PDF
R368 = RESISTOR: RES 2.2K 1/16W 5% 0402; Chkd/date: VASANTHA/061216; Crtd /date: BAVISH/021210; Custom_Duty: 15%; Customs_HS_Code: 85332119; Distributor_name: DIGIKEY; Distributor_part_number: 311-2.2KJRCT-ND; Footprint Path: Y:\MIS_DATABASE\Library\ALTIUM_TOOL\PCB_FOOTPRINTS\Altium_Footprint_Lib.PcbLib; Height: 0.40MM; Library Path: Y:\MIS_DATABASE\Library\ALTIUM_TOOL\SCHEMATICS_PARTS\MS_DISCRETE_Library.schlib; Mfr_name: YAGEO AMERICA; Mfr_part_number: RC0402JR-072K2L; Mistral Part No: 110010120018-R; Package: 0402; Part_type: RESISTORS\FIXED; Project: TE4; RoHS: RoHS; Temperature: -55°C+155°C; Tolerance: 5%; Voltage: NA; Wattage: 1/16W; Weight: 0.65mg; Datasheet: Y:\MIS_DATABASE\DATASHEETS\RESISTORS\RCXXXXL-SER_MAR18.PDF
R370 = RESISTOR: RES 1.5K 1/16W 5% 0402; Chkd/date: MANIRAJA/310718; Crtd /date: BAVISH/021210; Custom_Duty: 15%; Customs_HS_Code: 85332119; Distributor_name: DIGIKEY; Distributor_part_number: 311-1.5KJRCT-ND; Footprint Path: Y:\MIS_DATABASE\Library\ALTIUM_TOOL\PCB_FOOTPRINTS\Altium_Footprint_Lib.PcbLib; Height: 0.40MM; Library Path: Y:\MIS_DATABASE\Library\ALTIUM_TOOL\SCHEMATICS_PARTS\MS_DISCRETE_Library.schlib; Mfr_name: YAGEO AMERICA; Mfr_part_number: RC0402JR-071K5L; Mistral Part No: 110010120012-R; Package: 0402; Part_type: RESISTORS\FIXED; Project: TE4; RoHS: RoHS; Temperature: -55°C+155°C; Tolerance: 5%; Voltage: NA; Wattage: 1/16W; Weight: 0.65mg; Datasheet: Y:\MIS_DATABASE\DATASHEETS\RESISTORS\RCXXXXL-SER_MAR18.PDF
TP69 TP78 = TESTPOINT: TESTPOINT CIR 20 SMD; Chkd/date: SHREESHAIL/171006; Crtd /date: MAZHAR/171006; Custom_Duty: NA; Customs_HS_Code: NA; Distributor_name: NA; Distributor_part_number: NA; Footprint Path: Y:\MIS_DATABASE\Library\ALTIUM_TOOL\PCB_FOOTPRINTS\Altium_Footprint_Lib.PcbLib; Height: NA; Library Path: Y:\MIS_DATABASE\Library\ALTIUM_TOOL\SCHEMATICS_PARTS\MS_DISCRETE_Library.schlib; MECHANICAL 3D STEP FILE: NA; Mfr_name: LOCAL; Mistral Part No: NA; Package: SMD; Project: BT MODULE_CSRBC04; RoHS: NA; Temperature: NA; Tolerance: NA; Voltage: NA; Wattage: NA; Weight: NA; Datasheet: NA
U27 = TMUX154EDGSR_VSSOP10: IC ESD PROTECTED 2-CH 2:1 SWITCH WITH POWERED-OFF PROTECTION VSSOP10; Chkd/date: MANIRAJA/040918; Crtd /date: MANIRAJA/040918; Custom_Duty: 15%; Customs_HS_Code: 85423100; Distributor_name: DIGIKEY; Distributor_part_number: 296-48347-1-ND; Footprint Path: Y:\MIS_DATABASE\Library\ALTIUM_TOOL\PCB_FOOTPRINTS\Altium_Footprint_Lib.PcbLib; Height: 1.10MM; Library Path: Y:\MIS_DATABASE\Library\ALTIUM_TOOL\SCHEMATICS_PARTS\MS_ANALOG-APPLICATION_Library.schlib; Mfr_name: TEXAS INSTRUMENTS; Mistral Part No: 140118090001-R; Package: VSSOP10; Part_type: ICS\ANALOG\SWITCH; Project: DLRL_DFP_ATRUC CARD; RoHS: RoHS; Temperature: -40°C+85°C; Tolerance: NA; Voltage: NA; Wattage: NA; Weight: NA; Datasheet: Y:\MIS_DATABASE\DATASHEETS\ICS\ANALOG\TMUX154EXXX.PDF
U31 = SN74LVC1G08DBVRE4_SOT23-5: IC SINGLE 2-INPUT POSITIVE AND GATE SOT23-5; Chkd/date: SUHAS/221010; Crtd /date: USMAN/151008; Custom_Duty: 15%; Customs_HS_Code: 85423100; Distributor_name: DIGIKEY; Distributor_part_number: SN74LVC1G08DBVRE4-ND; Height: 1.45MM; Mfr_name: TEXAS INSTRUMENTS; Mistral Part No: 141009060026-R; Part_type: ICS\DIGITAL\GATES; Project: KHAN_MAIN; RoHS: Sb/ Br FREE; Temperature: -40°C+85°C; Datasheet: Y:\MIS_DATABASE\DATASHEETS\ICS\DIGITAL\GATES\SN74LVC1G08.PDF
U80 = DP83869HM_VQFN48: IC ETHERNET TRANSCEIVER 10/100/1000 WITH COPPER AND FIBRE INTERFACE VQFN48; Chkd/date: MANIRAJA/060519; Crtd /date: ALVY/060519; Custom_Duty: 15%; Customs_HS_Code: 85423100; Distributor_name: DIGIKEY; Distributor_part_number: 296-53377-1-ND; Footprint Path: Y:\MIS_DATABASE\Library\ALTIUM_TOOL\PCB_FOOTPRINTS\Altium_Footprint_Lib.PcbLib; Height: 1.00MM; Library Path: Y:\MIS_DATABASE\Library\ALTIUM_TOOL\SCHEMATICS_PARTS\MS_TELECOM_Library.schlib; Mfr_name: TEXAS INSTRUMENTS; Mistral Part No: 143019050002-R; Package: VQFN48; Part_type: ICS\TELECOM\TRANSCEIVER; Project: J7ES_ENET_DP83869HM_EXP; RoHS: RoHS; Temperature: -40°C+125°C; Tolerance: NA; Voltage: NA; Wattage: NA; Weight: NA; Datasheet: Y:\MIS_DATABASE\DATASHEETS\ICS\TELECOM\DP83869HM.PDF
ACC1-ACC3 ACC7 ACC8 ACC14 ACC15 = ACCESSORY: ACCESSORIE JUMPER SHORTING GOLD FLASH; Chkd/date: SUHAS\211010; Crtd /date: USMAN/301208; Distributor_name: DIGIKEY; Distributor_part_number: S9001-ND; Footprint Path: Y:\MIS_DATABASE\Library\ALTIUM_TOOL\PCB_FOOTPRINTS\Altium_Footprint_Lib.PcbLib; Library Path: Y:\MIS_DATABASE\Library\ALTIUM_TOOL\SCHEMATICS_PARTS\MS_MECHANICAL_Library.schlib; Mfr_name: SULLINS CONNECTOR; Mistral Part No: 160009030153-R; Part_type: ACCESSORIES; Project: SMART VIEW_NVR; RoHS: RoHS; Temperature: -55°C+105°C; Datasheet: Y:\MIS_DATABASE\DATASHEETS\MISC\MODULES\SPC02SYAN.PDF
ACC4 = ACCESSORY: ACCESSORIE CONNECTOR SHUNT 2X3 POS EDGE MOUNT SOCKET STRIP; Chkd/date: MANIRAJA/141117; Crtd /date: MANIRAJA/141117; Distributor_name: DIGIKEY; Distributor_part_number: SAM10620-ND; Mfr_name: SAMTEC; Mistral Part No: 160017110050-R; Part_type: ACCESSORIES; Project: TI_MAXIE_CPB; RoHS: RoHS; Temperature: -55°C+125°C; Datasheet: Y:\MIS_DATABASE\DATASHEETS\MISC\ACCESSORIES\SAMTEC-MNT-SER.PDF
ACC10 = ACCESSORY: ACCESSORIE BGA SOCKET AM64x MICROPROCESSOR BGA441; Chkd/date: MANIRAJA/220620; Crtd /date: ALVY/220620; Custom_Duty: NA; Customs_HS_Code: NA; Distributor_name: NA; Distributor_part_number: NA; Footprint Path: NA; Height: 10.93MM; Library Path: NA; Mfr_name: IRONWOOD ELECTRONICS; Mistral Part No: 160020060058; Package: BGA441; Part_type: ACCESSORIES; Project: AM64x-GP_EVM BRD; RoHS: NA; Temperature: -55°C+160°C; Tolerance: NA; Voltage: NA; Wattage: NA; Weight: 39530mg; Datasheet: Y:\MIS_DATABASE\DATASHEETS\MISC\ACCESSORIES\C19874_MAY20.PDF
ACC11 = ACCESSORY: ACCESSORIE TI EVM FLYERS STANDARD TERMS AND CONDITIONS; Chkd/date: MANIRAJA/221020; Crtd /date: ALVY/211020; Mfr_name: TEXAS INSTRUMENTS; Mistral Part No: 160020100056; Part_type: ACCESSORIES; Project: AM64x-IO LINK BRD
ACC12 = ACCESSORY: ACCESSORIE TI EVM FLYERS STANDARD WARRANTY NOTICE-BLACK AND WHITE; Chkd/date: MANIRAJA/221020; Crtd /date: ALVY/211020; Mfr_name: TEXAS INSTRUMENTS; Mistral Part No: 160020100057; Part_type: ACCESSORIES; Project: AM64x-IO LINK BRD
ACC13 = ACCESSORY: IC AM64 SoC MICROPROCESSOR BGA441; Custom_Duty: NA; Customs_HS_Code: NA; Distributor_name: NA; Distributor_part_number: NA; Footprint Path: NA; Height: 2.57MM; Library Path: NA; Mfr_name: TEXAS INSTRUMENTS; Mfr_part_number: AM6442ASFGGAALV; Mistral Part No: 141220040002; Package: BGA441; Part_type: ACCESSORIES; Project: AM64x-GP_EVM BRD; RoHS: NA; Temperature: -55°C+160°C; Tolerance: NA; Voltage: NA; Wattage: NA; Weight: 39530mg; Datasheet: Y:\MIS_DATABASE\DATASHEETS\MISC\ACCESSORIES\C19874_MAY20.PDF
FID1-FID3 = Fiducial
LBL1-LBL3 = ACCESSORY_THT-3-423-10: ACCESSORIE 1 WORKHORSE POLYSTER LABLE 0.25" X 1"; Chkd/date: MANIRAJA/270218; Crtd /date: ALVY/260218; Footprint Path: Y:\MIS_DATABASE\Library\ALTIUM_TOOL\PCB_FOOTPRINTS\Altium_Footprint_Lib.PcbLib; Library Path: Y:\MIS_DATABASE\Library\ALTIUM_TOOL\SCHEMATICS_PARTS\MS_MECHANICAL_Library.schlib; Mfr_name: BRADY; Mistral Part No: 160018020185; Part_type: ACCESSORIES; Project: TI_MAXIE_CPB
Logo1 Logo3 Logo4 = TI_Logo
Logo2 = FCC_disclaimer
M1-M6 = ACCESSORY: ACCESSORIE RECESSED BUMPER 19.05MM DIA; Chkd/date: MANIRAJA/110718; Crtd /date: MANIRAJA/110718; Distributor_name: DIGIKEY; Distributor_part_number: 36-728-ND; Mfr_name: KEYSTONE; Mistral Part No: 160018070042-R; Part_type: ACCESSORIES; Project: TI_MAXIE_CPB; RoHS: RoHS; Weight: 2042mg; Datasheet: Y:\MIS_DATABASE\DATASHEETS\MISC\ACCESSORIES\728.PDF
M10-M14 M19 = WASHER_PLAIN: PLAIN WASHER FOR M3 SS-316; Chkd/date: MANIRAJA/190218; Crtd /date: MANIRAJA/190218; Distributor_name: DIGIKEY; Distributor_part_number: 36-4692-ND; Footprint Path: Y:\MIS_DATABASE\Library\ALTIUM_TOOL\PCB_FOOTPRINTS\Altium_Footprint_Lib.PcbLib; Library Path: Y:\MIS_DATABASE\Library\ALTIUM_TOOL\SCHEMATICS_PARTS\MS_MECHANICAL_Library.schlib; Mfr_name: KEYSTONE; Mfr_part_number: 4692; Mistral Part No: 160018020078-R; Package: SS; Part_type: MECHANICAL\WASHERS; Project: TI_MAXIE_CPB; RoHS: RoHS; Datasheet: Y:\MIS_DATABASE\DATASHEETS\MISC\MECHANICAL\4692.PDF
MH1-MH6 = HEX_SPACER_FF: HEX SPACER FEMALE TO FEMALE M2.5 X 30MM; Chkd/date: MANIRAJA/190218; Crtd /date: MANIRAJA/190218; Distributor_name: DIGIKEY; Distributor_part_number: 732-10626-ND; Footprint Path: Y:\MIS_DATABASE\Library\ALTIUM_TOOL\PCB_FOOTPRINTS\Altium_Footprint_Lib.PcbLib; Height: 30.00MM; Library Path: Y:\MIS_DATABASE\Library\ALTIUM_TOOL\SCHEMATICS_PARTS\MS_MECHANICAL_Library.schlib; Mfr_name: WURTH ELECTRONICS; Mfr_part_number: 970300151; Mistral Part No: 160018020071-R; Package: SS; Part_type: MECHANICAL\SPACER; Project: TI_MAXIE_CPB; RoHS: RoHS; Datasheet: Y:\MIS_DATABASE\DATASHEETS\MISC\MECHANICAL\970XXX1.PDF
MH13-MH18 = SCREW_PAN: PHILLIPS PAN HEAD SCREW - M2.5 X 4 SS-316; Chkd/date: MANIRAJA/190218; Crtd /date: MANIRAJA/190218; Distributor_name: DIGIKEY; Distributor_part_number: 36-29300-ND; Footprint Path: Y:\MIS_DATABASE\Library\ALTIUM_TOOL\PCB_FOOTPRINTS\Altium_Footprint_Lib.PcbLib; Height: 4.00MM; Library Path: Y:\MIS_DATABASE\Library\ALTIUM_TOOL\SCHEMATICS_PARTS\MS_MECHANICAL_Library.schlib; Mfr_name: KEYSTONE; Mfr_part_number: 29300; Mistral Part No: 160018020076-R; Package: SS; Part_type: MECHANICAL\SCREWS; Project: TI_MAXIE_CPB; RoHS: RoHS; Datasheet: Y:\MIS_DATABASE\DATASHEETS\MISC\MECHANICAL\29300.PDF
MH19-MH24 = SCREW_PAN: PHILLIPS PAN HEAD SCREW - M2.5 X 12; Chkd/date: MANIRAJA/110718; Crtd /date: MANIRAJA/110718; Distributor_name: DIGIKEY; Distributor_part_number: 36-29304-ND; Height: 12.00MM; Mfr_name: KEYSTONE; Mfr_part_number: 29304; Mistral Part No: 160018070043-R; Part_type: ACCESSORIES; Project: TI_MAXIE_CPB; RoHS: RoHS; Datasheet: Y:\MIS_DATABASE\DATASHEETS\MISC\MECHANICAL\29304.PDF
PCB1 = PCB: AM64x EVM Bare PCB; Mfr_part_number: PROC101A

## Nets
DGND: C89.2 C99.2 C101.2 C104.2 C105.2 C106.2 C110.2 C111.2 C112.2 C114.2 C124.2 C128.2 C385.2 C389.2 C392.2 C394.2 C395.2 C397.2 C401.2 J21.B10(GND) Q14.2(S) Q16.2(S) Q21.2(S) R120.2 R121.2 R135.2 R341.2 R349.1 R359.2 R363.2 R367.2 R371.2 R385.2 R386.2 R563.2 U27.5(GND) U31.3(GND) U80.49(GND) ; also on sheet 2 3 4 5 6 7 8 9 10 11 12 13 14 15 16 17 18 19 20 21 22 23 24 25 26 27 28 29 30 40
VCC_3V3_SYS: C89.1 C99.1 C101.1 C104.1 C128.1 C385.1 C389.1 FB19.1 R126.1 R128.1 R340.1 R347.1 R366.1 R368.2 R369.1 R370.2 R380.2 R387.1 R388.1 R562.1 R615.2 R616.2 U27.10(VCC) U31.5(VCC) U80.18(VDDIO) U80.30(VDDIO) ; also on sheet 2 5 6 7 8 10 11 12 13 14 15 16 17 18 19 20 21 23 24 25 26 27 29 30 40
VDD_1V1: C105.1 C110.1 C112.1 C124.1 C394.1 C395.1 C401.1 U80.6(VDDA1P1) U80.31(VDD1P1) U80.39(VDD1P1) ; also on sheet 16 40
VDD_2V5: C106.1 C111.1 C114.1 C392.1 C397.1 U80.3(VDDA2P5) U80.9(VDDA2P5) ; also on sheet 2 16 40
CPSW_RGMII1_MDC: U27.7(B1) ; also on sheet 2 18
CPSW_RGMII1_MDIO: U27.3(A1) ; also on sheet 2 18
GPIO_RGMII2_RST: R371.1 R380.1 U31.1(A) ; also on sheet 13
PORz_OUT: U31.2(B) ; also on sheet 2 12 24 29 40
PRG1_ETH2_D0M: J21.B2(TD1-_2) U80.2(TD_M_A)
PRG1_ETH2_D0P: J21.B1(TD1+_2) U80.1(TD_P_A)
PRG1_ETH2_D1M: J21.B4(TD2-_2) U80.5(TD_M_B)
PRG1_ETH2_D1P: J21.B3(TD2+_2) U80.4(TD_P_B)
PRG1_ETH2_D2M: J21.B6(TD3-_2) U80.8(TD_M_C)
PRG1_ETH2_D2P: J21.B5(TD3+_2) U80.7(TD_P_C)
PRG1_ETH2_D3M: J21.B8(TD4-_2) U80.11(TD_M_D)
PRG1_ETH2_D3P: J21.B7(TD4+_2) U80.10(TD_P_D)
PRG1_ETH2_GPIO_1: R340.2 R341.1 R617.2 U80.22(JTAG_TDO/GPIO_1)
PRG1_ETH2_LED1: J21.B11 Q14.3(D)
PRG1_ETH2_LED2: J21.B14 Q21.3(D) R616.1
PRG1_ETH2_LED3: J21.B13 Q16.3(D) R615.1
PRG1_ETH2_LED_1000/RX_ER: R343.2 R386.1 R388.2 U80.46(LED_1/RX_ER) ; also on sheet 18
PRG1_ETH2_LED_ACT: R324.1 R385.1 R387.2 U80.45(LED_2/GPIO_0)
PRG1_ETH2_LED_LINK: R562.2 R563.1 U80.47(LED_0) ; also on sheet 18
PRG1_MDIO_MDC: U27.8(B0) ; also on sheet 18 40
PRG1_MDIO_MDIO: U27.2(A0) ; also on sheet 18 40
PRG1_RGMII2_ETH2_CLK: U80.20(XI) ; also on sheet 11
PRG1_RGMII2_ETH2_CLK_OUT: TP78.1(TP) U80.40(CLK_OUT)
PRG1_RGMII2_ETH2_RBIAS: R349.2 U80.12(RBIAS)
PRG1_RGMII2_FET_ENn: R121.1 U27.9(~{EN})
PRG1_RGMII2_FET_SEL: R120.1 U27.1(SEL) ; also on sheet 13
PRG1_RGMII2_MDC: R369.2 U27.6(B) U80.42(MDC)
PRG1_RGMII2_MDIO: R370.1 U27.4(A) U80.41(MDIO)
PRG1_RGMII2_RD0: R126.2 R359.1 U80.33(RX_D0) ; also on sheet 18
PRG1_RGMII2_RD1: R128.2 R363.1 U80.34(RX_D1) ; also on sheet 18
PRG1_RGMII2_RD2: U80.35(RX_D2) ; also on sheet 18
PRG1_RGMII2_RD3: U80.36(RX_D3) ; also on sheet 18
PRG1_RGMII2_RESETn: R367.1 U31.4(Y) U80.43(RESET_N)
PRG1_RGMII2_RX_CTL: R135.1 R366.2 U80.38(RX_CTRL/RX_DV) ; also on sheet 18
PRG1_RGMII2_RXC: U80.32(RX_CLK) ; also on sheet 18
PRG1_RGMII2_TD0: U80.28(TX_D0) ; also on sheet 18
PRG1_RGMII2_TD1: U80.27(TX_D1) ; also on sheet 18
PRG1_RGMII2_TD2: U80.26(TX_D2) ; also on sheet 18
PRG1_RGMII2_TD3: U80.25(TX_D3) ; also on sheet 18
PRG1_RGMII2_TX_CTL: U80.37(TX_CTRL/TX_EN) ; also on sheet 18
PRG1_RGMII2_TXC: U80.29(GTX_CLK/TX_CLK) ; also on sheet 18
PRG1_RGMII_INTn: R368.1 U80.44(INT_N/PWDN_N) ; also on sheet 2 12 40
PRG_EARTH: J21.SH3 J21.SH4 ; also on sheet 40
N18117332: Q14.1(G) R324.2
N18117389: Q16.1(G) R343.1
N24754956: TP69.1(TP) U80.13(VDDA1P8_1) U80.48(VDDA1P8_2)
N27217693: FB19.2 J21.B9(VCC)
N27218087: J21.B12 R347.2
N28854850: Q21.1(G) R617.1

Not connected (* = marked no-connect by the designer): U80 14(SON)* 15(SOP)* 16(SIP)* 17(SIN)* 19(XO)* 21(JTAG_CLK/TX_ER)* 23(JTAG_TMS)* 24(JTAG_TDI/SD)*

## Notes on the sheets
sheet 31
- HARDWARE SCHEMATICS
- SCREWS
- JUMPERs
- STANDOFFs
- ASSEMBLY NOTES
- 1. All MSL components should be baked as per JEDEC standard.
  2. PCB should be baked at 120 degree for 8 hours.
  3. Board assembly must comply with workmanship standards.
  IPC-A-610 Class 2, unless otherwise specified.
  4. These assemblies are ESD sensitive, ESD precautions
  shall be observed.
  5. These assemblies must be clean and free from flux and
  all contaminants. Use of no clean flux is not acceptable.
  6. Provide serial numbers to the assembled boards for identification.
  7. The assembled board are wrapped in ESD Covers(individual) and
  packed securely before shipment.
- WASHER's
- FIDUCIALS
- RUBBER FEET
- TI EVM FLYERS
- Socket & Processor as Accessories
- BARE PCB
- LABELS
- LOGOs
- ORDERABLE PART NO
- Texas Intruments
- For Evaluation only; not FCC approved for resale
- WEEE Mark
- CE Mark
- Board Serial No.
- Orderable part number
- Variant
- Label Text
- 001
- TMDS64GPEVM
- Assembly Revision
- 002
- TMDS243GPEVM
- 003
- 004
sheet 32
- GPIO  MAPPING TABLE
sheet 33
- I2C TREE
sheet 34
- POWER SEQUENCE
- POWER UP SEQUENCE
- 12V
- 5V0
- 3V3_PREREG
- 3V3_SYS
- 2V5 ,2V8
- 1V0 ,1V1
- 1V8
- 1V8 ANALOG
- 1V2
- 0V75
- 0V85
- MCU_PORz
- POWER DOWN SEQUENCE
- 5V0
- 3V3_SYS,2V5,
  1V1 ,1V0
- 1V8 ANALOG,
  1V8_IO,2V8
- 1V2
- 0V85
- 0V75
- MCU_PORz
- 3V3_PREREG
sheet 35
- POWER FLOW DIAGRAM
- CORE SUPPLY
- ARRAY CORE SUPPLY
- STEERING RESISTORS
- 0.75 VDD_CORE
- 0.85 VDDR_CORE&OTHERS
- R2 & R4 INSTALLED
- 0.8 VDD_CORE
- 0.85 VDDR_CORE&OTHERS
- R2 & R4 INSTALLED
- 0.8 VDD_CORE & OTHERS
- 0.85 VDDR_CORE
- R1 & R4 INSTALLED
- 0.85 VDD_CORE,VDDR_CORE&OTHERS
- NONE
- R1 & R3 INSTALLED
sheet 36
- BLOCK DIAGRAM_AM64x_EVM
sheet 37
- AM64x/AM243x  GENERAL PURPOSE EVM BOARD
- PROC101A
- TABLE OF CONTENTS
- PAGE
- CONTENTS
- PAGE
- CONTENTS
- REV
- A
- 01
- TABLE OF CONTENTS
- 35
- DEBOUNCE CIRCUIT & VOLTAGE SUPERVISOR
- VER
- 0.6
- 02
- REVISION HISTORY
- 36
- MAIN INPUT 12V DC
- 03
- BLOCK DIAGRAM AM64x EVM BOARD
- 37
- DUAL & PRE_REG POWER SUPPLY
- 04
- BLOCK DIAGRAM - XDS110
- 38
- SoC POWER SUPPLY
- 05
- POWER FLOW DIAGRAM
- 39
- PERIPHERAL POWER SUPPLY
- 06
- POWER SEQUENCE
- 40
- HARDWARE SCHEMATICS
- 07
- GPIO MAPPING TABLE
- 08
- I2C TREE
- 09
- SOC POWER
- 10
- SOC POWER CAPS
- 11
- SOC VSS
- 12
- DDR INTERFACE
- 13
- eMMC FLASH AND SDCARD INTERFACE
- 14
- OSPI FLASH
- 15
- EEPROM,PRESENCE DETECTION & TEMP SENSOR
- 16
- CPSW RGMII_1 ETHERNET PHY
- 17
- ICSSG RGMII_2 ETHERNET PHY
- 18
- ICSSG RGMII_1 ETHERNET PHY
- 19
- TEST AUTOMATION
- 20
- BOOT MODE BUFFER & SWITCHES
- 21
- CURRENT MONITORING DEVICES
- 22
- XDS110  DEBUGGER
- 23
- JTAG BUFFER
- 24
- MIPI 60 PIN CONNECTOR
- 25
- USB 2.0 INTERFACE
- 26
- FT4232 UART TO USB BRIDGE
- 27
- HSE BOARD CONNECTOR
- 28
- GPMC & FSI CONNECTOR
- 29
- CAN & DISPLAY INTERFACE
- 30
- PCIe INTERFACE
- 31
- ETHERNET PHY & PCIe CLOCK GENERATOR
- 32
- ETHERNET LEDs
- 33
- IO EXPANDER & TEST HEADER
- 34
- MCU GENERAL&SAFETY CONNECTOR
sheet 38
- REVISION HISTORY
- VER #
- DATE
- DESCRIPTION OF CHANGES
- AUTHOR
- REVIEWED  BY
- APPROVED  BY
- 0.1
- 10th FEBRUARY 2021
- Drafted from "PROC101E2_SCH" document.
- Mistral Design Team
- AJIT MB
- AJIT MB
- 1.C400,C441 changed from 0402 to 0603
  2.LD26 changed from red to green is followed as mentioned in the data manual
  3.Capacitor Divider with value 27pF is introduced at the XI input of U15
     (CPSW Ethernet PHY) as the source/driver is 3.3V and XI input accepts an
     input of 1.5V to 1.9V P-P.
  4.MUX IC U78 is removed and the CPSW_RGMII1_MDIO/MDC pins are directly
     connected to SoC pins P5 & R2 Respectively.
  5.R370 is mounted with 1.5K resistor
  6.R183 made DNI as the desired input to the inverter U47 should be high
  7.R605,a pull-down resistor of value 499E 1% is added on the USB0_RCALIB
     as per the recommendation in the SoC datasheet
  8. 4.7K Pull up resistors are added to the 4 UART TX pins (R608,R609,R610,R611)
  9.R606,a 4.7K Pull down resistor is added at pin MCU_PORz to Ensure that the
     MCU_PORz is low at the start of the power down sequence
  10.R348 changed from 1K to 10K
  11.DC Jack changed from PJ-063AH to PJ-080BH
  12.J21 changed from 7499151120 to LPJG17512AONL
  13.Q20,Q21,R612, R613, R614, R615, R616, R617 added for status leds of ethernet phys
  14.R313,R316 removed
  15.Display changed to OSD9616P1673-30
- 0.2
- 11th FEBRUARY 2021
- Mistral Design Team
- AJIT MB
- AJIT MB
- 0.3
- 18th FEBRUARY 2021
- 1.R622,R623-1K pull down resistors ; R624,R625-1.5K pull up resistors ; R632
   added in PCIE clock section
  2. U39 changed to TPS22918DBVR to reduce ramp down time of VDD_MMC1;R174 removed.
  3.J39,J40-1x2 Header used in JTAG EMU0/1 signals to enable WIR mode or
   boundary scan manually. R630,R631, R634,R635 added as pull up and pull down resistors
  4.R455,R458,R460,R461 made DNI. ACC14 ,ACC15 added.
  5.FSI TX and RX signals swapped and pin9 of J7 made no connect
- Mistral Design Team
- AJIT MB
- AJIT MB
- 25th FEBRUARY 2021
- 1.CDCI6214 added to provide reference clock to both PCIe connector and and SoC side
  2.R448 changed from 10E to 100E
  3.R685 100E Series Resistor added on JTAG_TRST# near cTI 20pin connector
  4.C529 added in JTAG_TRST# from MIPI and CTI 20 connector
  5. Added 10K PU resistor on JTAG_TCK, JTAG_TMS, and JTAG_TDI.  Added 10K PD  resistor
  on JTAG_TRST#
  6.Added DNI 10K pull-up  on MMC1_CLK .  Added DNI 10K pull-down on MMC0_CLK and
  MMC1_CLK.
- AJIT MB
- AJIT MB
- 0.4
- Mistral Design Team
- 1.R622,R623-1K pull down resistors ; R624,R625-1.5K pull up resistors made as DNI
  2. C502 / C503 changed to 0E 0402 Resistors -R679, R680
  3. Added Resistors R661,R662, R665,R666,R667,R668 for PCIe CLK selection
- 0.5
- 28th FEBRUARY 2021
- Mistral Design Team
- AJIT MB
- AJIT MB
- 1.Added AM243x SoC variant
  2. Changed core voltage supply to 0.85V in AM243x variant
- 0.6
- 30th MARCH 2021
- Mistral Design Team
- AJIT MB
- AJIT MB
sheet 39
- ICSSG1 - RGMII 2
- Dual RJ45 CON With Integrated Magnetics
- Decaps
- STRAPPING RESISTORS
- PRG1 ETH2 RESET
- PHY ADDRESS = 00011
- Auto-negotiation, 10/100/1000 advertised, Auto-MDI-X
- RGMII to Copper (1000BaseT/100Base-TX/10Base-Te)
- Off Page Connections
- PRG1 MDC/MDIO FET SWITCH
- To Processor
- PRG1_ETHERNET - 2 SPEED & ACTIVITY  LED 's DRIVERS
- From Processor
- From CPSW SW
- From IO Expander
- TMUX154EDGSR Truth Table
- From Clock Buffer
